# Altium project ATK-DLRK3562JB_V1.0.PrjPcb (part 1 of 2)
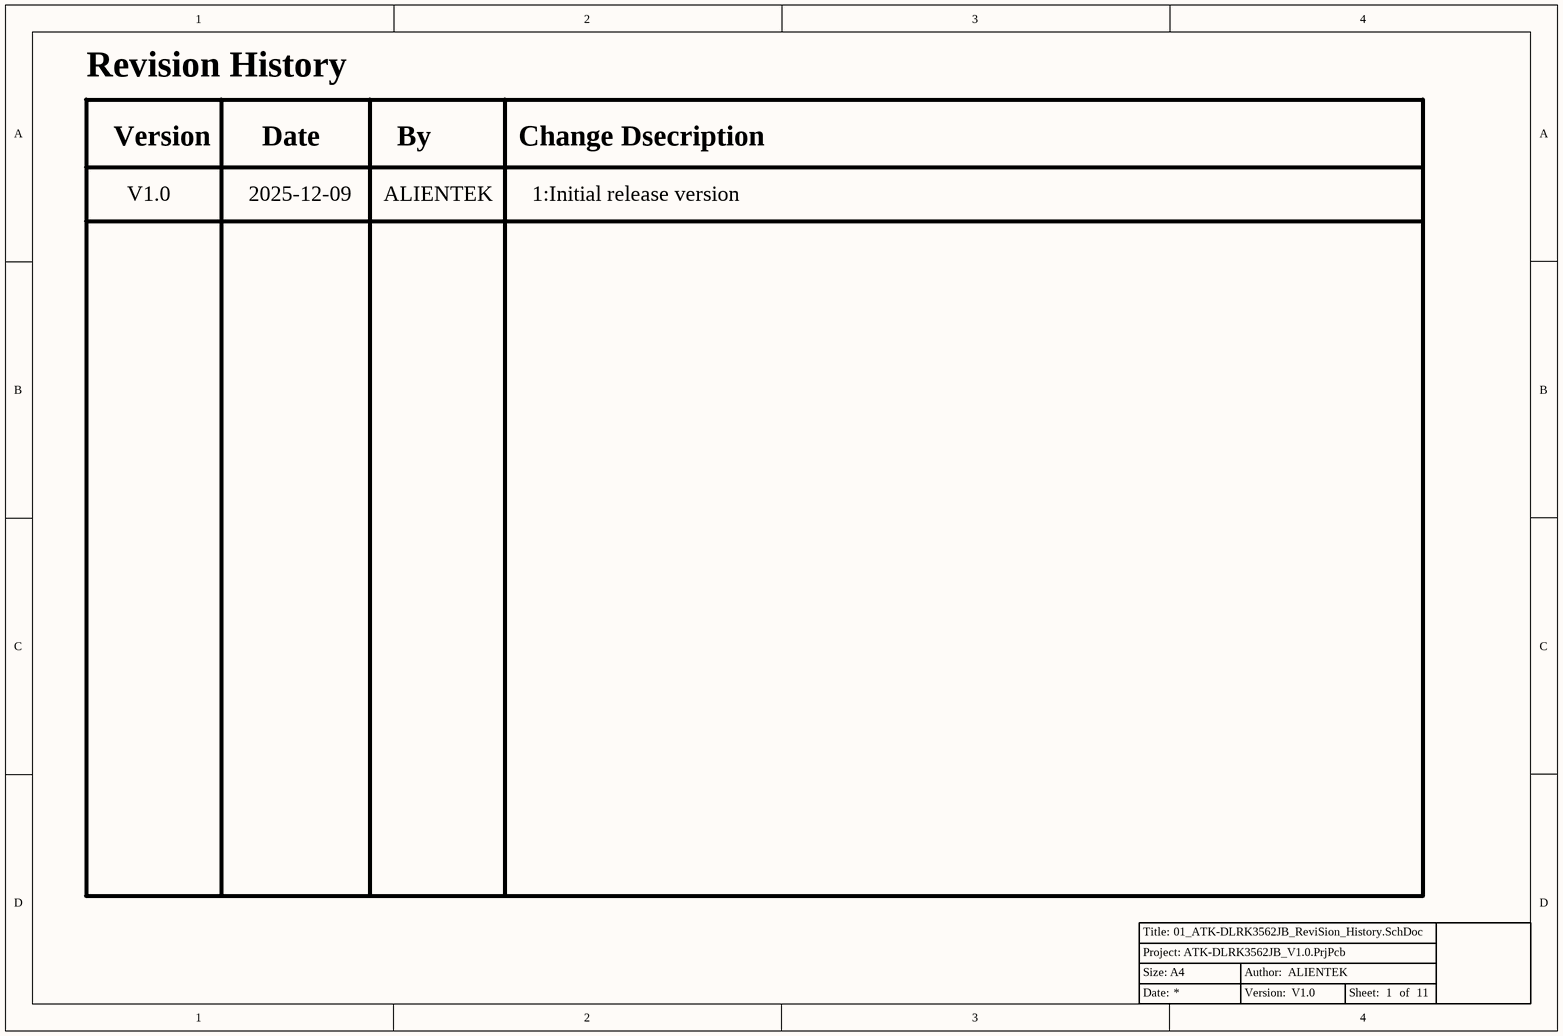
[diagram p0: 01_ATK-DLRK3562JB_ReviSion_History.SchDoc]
11 sheets, 441 parts. Net scope: global (net labels, ports and power ports of the same name join across sheets).
Sheets:
  01_ATK-DLRK3562JB_ReviSion_History.SchDoc
  02_ATK-DLRK3562JB_CORE_BOARD.SchDoc
  03_ATK-DLRK3562JB_POWER_UART.SchDoc
  04_ATK-DLRK3562JB_DEVICE1.SchDoc
  05_ATK-DLRK3562JB_DEVICE2.SchDoc
  06_ATK-DLRK3562JB_4G_HUB.SchDoc
  07_ATK-DLRK3562JB_WIFI_TF_OTG_PINOUT.SchDoc
  08_ATK-DLRK3562JB_PCIE_AUDIO.SchDoc
  09_ATK-DLRK3562JB_LCD_CAMERA.SchDoc
  10_ATK-DLRK3562JB_RMII_NET.SchDoc
  11_ATK-DLRK3562JB_RGMII_NET.SchDoc

## Sheet 01_ATK-DLRK3562JB_ReviSion_History.SchDoc
size A4; Author: ALIENTEK; Revision: 0; SheetNumber: 1; SheetTotal: 11; Version: V1.0; SheetSize: A4

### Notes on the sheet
- Revision History
- Version
- Date
- By
- Change Dsecription
- V1.0
- 2025-12-09
- ALIENTEK
- 1:Initial release version

## Sheet 02_ATK-DLRK3562JB_CORE_BOARD.SchDoc
size A3; Date: 13; Author: ALIENTEK; Revision: 0; SheetNumber: 2; SheetTotal: 11; Version: V1.0; SheetSize: A3
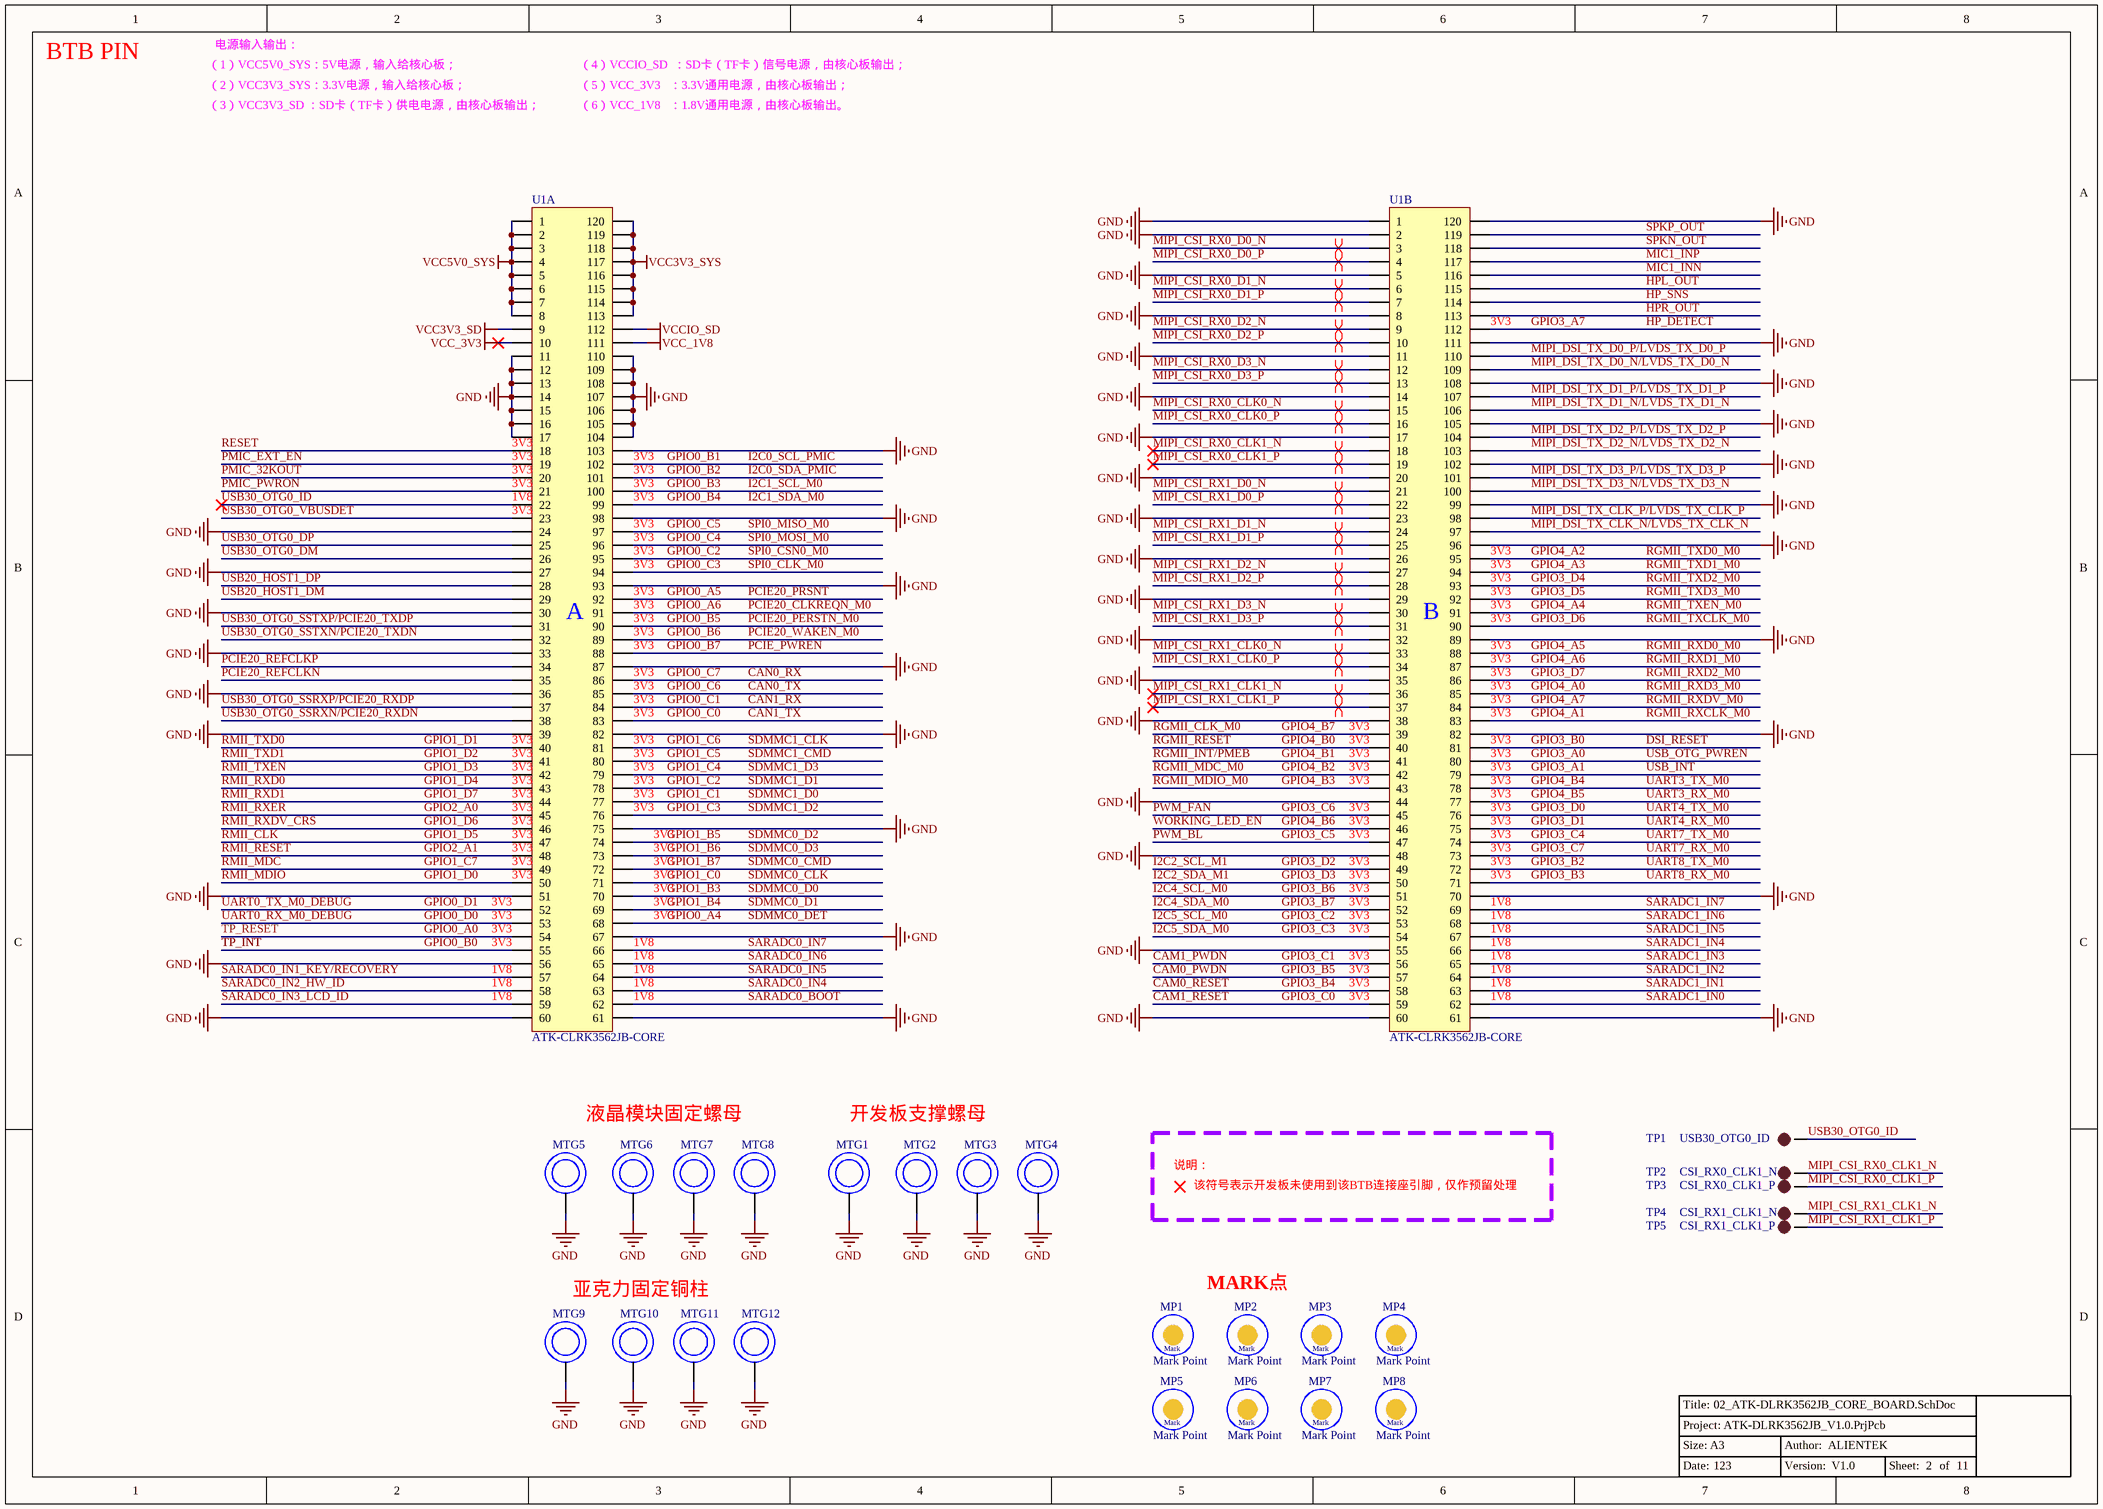
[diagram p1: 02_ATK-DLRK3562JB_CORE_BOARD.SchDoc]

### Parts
MP1  Mark Point  [FD_MARK]
MP2  Mark Point  [FD_MARK]
MP3  Mark Point  [FD_MARK]
MP4  Mark Point  [FD_MARK]
MP5  Mark Point  [FD_MARK]
MP6  Mark Point  [FD_MARK]
MP7  Mark Point  [FD_MARK]
MP8  Mark Point  [FD_MARK]
MTG1  螺母(M3*6,贴片螺母柱,白色,SMTSO-M3-6ET)  [M3-6ET]  (value not drawn)
MTG2  螺母(M3*6,贴片螺母柱,白色,SMTSO-M3-6ET)  [M3-6ET]  (value not drawn)
MTG3  螺母(M3*6,贴片螺母柱,白色,SMTSO-M3-6ET)  [M3-6ET]  (value not drawn)
MTG4  螺母(M3*6,贴片螺母柱,白色,SMTSO-M3-6ET)  [M3-6ET]  (value not drawn)
MTG5  螺母(M3*6,贴片螺母柱,白色,SMTSO-M3-6ET)  [M3*23+6]  (value not drawn)
MTG6  螺母(M3*6,贴片螺母柱,白色,SMTSO-M3-6ET)  [M3*23+6]  (value not drawn)
MTG7  螺母(M3*6,贴片螺母柱,白色,SMTSO-M3-6ET)  [M3*23+6]  (value not drawn)
MTG8  螺母(M3*6,贴片螺母柱,白色,SMTSO-M3-6ET)  [M3*23+6]  (value not drawn)
MTG9  螺母(M3*6,贴片螺母柱,白色,SMTSO-M3-6ET)  [M3-6ET]  (value not drawn)
MTG10  螺母(M3*6,贴片螺母柱,白色,SMTSO-M3-6ET)  [M3-6ET]  (value not drawn)
MTG11  螺母(M3*6,贴片螺母柱,白色,SMTSO-M3-6ET)  [M3-6ET]  (value not drawn)
MTG12  螺母(M3*6,贴片螺母柱,白色,SMTSO-M3-6ET)  [M3-6ET]  (value not drawn)
TP1  USB30_OTG0_ID  [TEST 1]
TP2  CSI_RX0_CLK1_N  [TEST 1]
TP3  CSI_RX0_CLK1_P  [TEST 1]
TP4  CSI_RX1_CLK1_N  [TEST 1]
TP5  CSI_RX1_CLK1_P  [TEST 1]
U1  ATK-CLRK3562JB-CORE  [ATK-CLRK3562JB-CORE]  (parts A,B of 2)

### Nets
GND: MTG1.1 MTG2.1 MTG3.1 MTG4.1 MTG5.1 MTG6.1 MTG7.1 MTG8.1 MTG9.1 MTG10.1 MTG11.1 MTG12.1 U1.A11(11) U1.A12(12) U1.A13(13) U1.A14(14) U1.A15(15) U1.A16(16) U1.A17(17) U1.A24(24) U1.A27(27) U1.A30(30) U1.A33(33) U1.A36(36) U1.A39(39) U1.A51(51) U1.A56(56) U1.A60(60) U1.A61(61) U1.A67(67) U1.A75(75) U1.A82(82) U1.A87(87) U1.A93(93) U1.A98(98) U1.A103(103) U1.A104(104) U1.A105(105) U1.A106(106) U1.A107(107) U1.A108(108) U1.A109(109) U1.A110(110) U1.B1(1) U1.B2(2) U1.B5(5) U1.B8(8) U1.B11(11) U1.B14(14) U1.B17(17) U1.B20(20) U1.B23(23) U1.B26(26) U1.B29(29) U1.B32(32) U1.B35(35) U1.B38(38) U1.B44(44) U1.B48(48) U1.B55(55) U1.B60(60) U1.B61(61) U1.B70(70) U1.B82(82) U1.B89(89) U1.B96(96) U1.B99(99) U1.B102(102) U1.B105(105) U1.B108(108) U1.B111(111) U1.B120(120)
VCC3V3_SD: U1.A9(9)
VCC3V3_SYS: U1.A113(113) U1.A114(114) U1.A115(115) U1.A116(116) U1.A117(117) U1.A118(118) U1.A119(119) U1.A120(120)
VCC5V0_SYS: U1.A1(1) U1.A2(2) U1.A3(3) U1.A4(4) U1.A5(5) U1.A6(6) U1.A7(7) U1.A8(8)
VCC_1V8: U1.A111(111)
VCC_3V3: U1.A10(10)
VCCIO_SD: U1.A112(112)
CAM0_PWDN: U1.B57(57)  [also labelled GPIO3_B5]
CAM0_RESET: U1.B58(58)  [also labelled GPIO3_B4]
CAM1_PWDN: U1.B56(56)  [also labelled GPIO3_C1]
CAM1_RESET: U1.B59(59)  [also labelled GPIO3_C0]
CAN0_RX: U1.A86(86)  [also labelled GPIO0_C7]
CAN0_TX: U1.A85(85)  [also labelled GPIO0_C6]
CAN1_RX: U1.A84(84)  [also labelled GPIO0_C1]
CAN1_TX: U1.A83(83)  [also labelled GPIO0_C0]
DSI_RESET: U1.B81(81)  [also labelled GPIO3_B0]
GPIO0_A0: U1.A54(54)  [also labelled TP_RESET]
GPIO0_A4: U1.A68(68)  [also labelled SDMMC0_DET]
GPIO0_A5: U1.A92(92)  [also labelled PCIE20_PRSNT]
GPIO0_A6: U1.A91(91)  [also labelled PCIE20_CLKREQN_M0]
GPIO0_B0: U1.A55(55)  [also labelled TP_INT]
GPIO0_B1: U1.A102(102)  [also labelled I2C0_SCL_PMIC]
GPIO0_B2: U1.A101(101)  [also labelled I2C0_SDA_PMIC]
GPIO0_B3: U1.A100(100)  [also labelled I2C1_SCL_M0]
GPIO0_B4: U1.A99(99)  [also labelled I2C1_SDA_M0]
GPIO0_B5: U1.A90(90)  [also labelled PCIE20_PERSTN_M0]
GPIO0_B6: U1.A89(89)  [also labelled PCIE20_WAKEN_M0]
GPIO0_B7: U1.A88(88)  [also labelled PCIE_PWREN]
GPIO0_C2: U1.A95(95)  [also labelled SPI0_CSN0_M0]
GPIO0_C3: U1.A94(94)  [also labelled SPI0_CLK_M0]
GPIO0_C4: U1.A96(96)  [also labelled SPI0_MOSI_M0]
GPIO0_C5: U1.A97(97)  [also labelled SPI0_MISO_M0]
GPIO0_D0: U1.A53(53)  [also labelled UART0_RX_M0_DEBUG]
GPIO0_D1: U1.A52(52)  [also labelled UART0_TX_M0_DEBUG]
GPIO1_B3: U1.A70(70)  [also labelled SDMMC0_D0]
GPIO1_B4: U1.A69(69)  [also labelled SDMMC0_D1]
GPIO1_B5: U1.A74(74)  [also labelled SDMMC0_D2]
GPIO1_B6: U1.A73(73)  [also labelled SDMMC0_D3]
GPIO1_B7: U1.A72(72)  [also labelled SDMMC0_CMD]
GPIO1_C0: U1.A71(71)  [also labelled SDMMC0_CLK]
GPIO1_C1: U1.A77(77)  [also labelled SDMMC1_D0]
GPIO1_C2: U1.A78(78)  [also labelled SDMMC1_D1]
GPIO1_C3: U1.A76(76)  [also labelled SDMMC1_D2]
GPIO1_C4: U1.A79(79)  [also labelled SDMMC1_D3]
GPIO1_C5: U1.A80(80)  [also labelled SDMMC1_CMD]
GPIO1_C6: U1.A81(81)  [also labelled SDMMC1_CLK]
GPIO1_C7: U1.A49(49)  [also labelled RMII_MDC]
GPIO1_D0: U1.A50(50)  [also labelled RMII_MDIO]
GPIO1_D1: U1.A40(40)  [also labelled RMII_TXD0]
GPIO1_D2: U1.A41(41)  [also labelled RMII_TXD1]
GPIO1_D3: U1.A42(42)  [also labelled RMII_TXEN]
GPIO1_D4: U1.A43(43)  [also labelled RMII_RXD0]
GPIO1_D5: U1.A47(47)  [also labelled RMII_CLK]
GPIO1_D6: U1.A46(46)  [also labelled RMII_RXDV_CRS]
GPIO1_D7: U1.A44(44)  [also labelled RMII_RXD1]
GPIO2_A0: U1.A45(45)  [also labelled RMII_RXER]
GPIO2_A1: U1.A48(48)  [also labelled RMII_RESET]
GPIO3_A0: U1.B80(80)  [also labelled USB_OTG_PWREN]
GPIO3_A1: U1.B79(79)  [also labelled USB_INT]
GPIO3_A7: U1.B112(112)  [also labelled HP_DETECT]
GPIO3_B2: U1.B72(72)  [also labelled UART8_TX_M0]
GPIO3_B3: U1.B71(71)  [also labelled UART8_RX_M0]
GPIO3_B6: U1.B51(51)  [also labelled I2C4_SCL_M0]
GPIO3_B7: U1.B52(52)  [also labelled I2C4_SDA_M0]
GPIO3_C2: U1.B53(53)  [also labelled I2C5_SCL_M0]
GPIO3_C3: U1.B54(54)  [also labelled I2C5_SDA_M0]
GPIO3_C4: U1.B74(74)  [also labelled UART7_TX_M0]
GPIO3_C5: U1.B47(47)  [also labelled PWM_BL]
GPIO3_C6: U1.B45(45)  [also labelled PWM_FAN]
GPIO3_C7: U1.B73(73)  [also labelled UART7_RX_M0]
GPIO3_D0: U1.B76(76)  [also labelled UART4_TX_M0]
GPIO3_D1: U1.B75(75)  [also labelled UART4_RX_M0]
GPIO3_D2: U1.B49(49)  [also labelled I2C2_SCL_M1]
GPIO3_D3: U1.B50(50)  [also labelled I2C2_SDA_M1]
GPIO3_D4: U1.B93(93)  [also labelled RGMII_TXD2_M0]
GPIO3_D5: U1.B92(92)  [also labelled RGMII_TXD3_M0]
GPIO3_D6: U1.B90(90)  [also labelled RGMII_TXCLK_M0]
GPIO3_D7: U1.B86(86)  [also labelled RGMII_RXD2_M0]
GPIO4_A0: U1.B85(85)  [also labelled RGMII_RXD3_M0]
GPIO4_A1: U1.B83(83)  [also labelled RGMII_RXCLK_M0]
GPIO4_A2: U1.B95(95)  [also labelled RGMII_TXD0_M0]
GPIO4_A3: U1.B94(94)  [also labelled RGMII_TXD1_M0]
GPIO4_A4: U1.B91(91)  [also labelled RGMII_TXEN_M0]
GPIO4_A5: U1.B88(88)  [also labelled RGMII_RXD0_M0]
GPIO4_A6: U1.B87(87)  [also labelled RGMII_RXD1_M0]
GPIO4_A7: U1.B84(84)  [also labelled RGMII_RXDV_M0]
GPIO4_B0: U1.B40(40)  [also labelled RGMII_RESET]
GPIO4_B1: U1.B41(41)  [also labelled RGMII_INT/PMEB]
GPIO4_B2: U1.B42(42)  [also labelled RGMII_MDC_M0]
GPIO4_B3: U1.B43(43)  [also labelled RGMII_MDIO_M0]
GPIO4_B4: U1.B78(78)  [also labelled UART3_TX_M0]
GPIO4_B5: U1.B77(77)  [also labelled UART3_RX_M0]
GPIO4_B6: U1.B46(46)  [also labelled WORKING_LED_EN]
GPIO4_B7: U1.B39(39)  [also labelled RGMII_CLK_M0]
HP_SNS: U1.B114(114)
HPL_OUT: U1.B115(115)
HPR_OUT: U1.B113(113)
MIC1_INN: U1.B116(116)
MIC1_INP: U1.B117(117)
MIPI_CSI_RX0_CLK0_N: U1.B15(15)
MIPI_CSI_RX0_CLK0_P: U1.B16(16)
MIPI_CSI_RX0_CLK1_N: TP2.1 U1.B18(18)
MIPI_CSI_RX0_CLK1_P: TP3.1 U1.B19(19)
MIPI_CSI_RX0_D0_N: U1.B3(3)
MIPI_CSI_RX0_D0_P: U1.B4(4)
MIPI_CSI_RX0_D1_N: U1.B6(6)
MIPI_CSI_RX0_D1_P: U1.B7(7)
MIPI_CSI_RX0_D2_N: U1.B9(9)
MIPI_CSI_RX0_D2_P: U1.B10(10)
MIPI_CSI_RX0_D3_N: U1.B12(12)
MIPI_CSI_RX0_D3_P: U1.B13(13)
MIPI_CSI_RX1_CLK0_N: U1.B33(33)
MIPI_CSI_RX1_CLK0_P: U1.B34(34)
MIPI_CSI_RX1_CLK1_N: TP4.1 U1.B36(36)
MIPI_CSI_RX1_CLK1_P: TP5.1 U1.B37(37)
MIPI_CSI_RX1_D0_N: U1.B21(21)
MIPI_CSI_RX1_D0_P: U1.B22(22)
MIPI_CSI_RX1_D1_N: U1.B24(24)
MIPI_CSI_RX1_D1_P: U1.B25(25)
MIPI_CSI_RX1_D2_N: U1.B27(27)
MIPI_CSI_RX1_D2_P: U1.B28(28)
MIPI_CSI_RX1_D3_N: U1.B30(30)
MIPI_CSI_RX1_D3_P: U1.B31(31)
MIPI_DSI_TX_CLK_N/LVDS_TX_CLK_N: U1.B97(97)
MIPI_DSI_TX_CLK_P/LVDS_TX_CLK_P: U1.B98(98)
MIPI_DSI_TX_D0_N/LVDS_TX_D0_N: U1.B109(109)
MIPI_DSI_TX_D0_P/LVDS_TX_D0_P: U1.B110(110)
MIPI_DSI_TX_D1_N/LVDS_TX_D1_N: U1.B106(106)
MIPI_DSI_TX_D1_P/LVDS_TX_D1_P: U1.B107(107)
MIPI_DSI_TX_D2_N/LVDS_TX_D2_N: U1.B103(103)
MIPI_DSI_TX_D2_P/LVDS_TX_D2_P: U1.B104(104)
MIPI_DSI_TX_D3_N/LVDS_TX_D3_N: U1.B100(100)
MIPI_DSI_TX_D3_P/LVDS_TX_D3_P: U1.B101(101)
PCIE20_REFCLKN: U1.A35(35)
PCIE20_REFCLKP: U1.A34(34)
PMIC_32KOUT: U1.A20(20)
PMIC_EXT_EN: U1.A19(19)
PMIC_PWRON: U1.A21(21)
RESET: U1.A18(18)
SARADC0_BOOT: U1.A62(62)
SARADC0_IN1_KEY/RECOVERY: U1.A57(57)
SARADC0_IN2_HW_ID: U1.A58(58)
SARADC0_IN3_LCD_ID: U1.A59(59)
SARADC0_IN4: U1.A63(63)
SARADC0_IN5: U1.A64(64)
SARADC0_IN6: U1.A65(65)
SARADC0_IN7: U1.A66(66)
SARADC1_IN0: U1.B62(62)
SARADC1_IN1: U1.B63(63)
SARADC1_IN2: U1.B64(64)
SARADC1_IN3: U1.B65(65)
SARADC1_IN4: U1.B66(66)
SARADC1_IN5: U1.B67(67)
SARADC1_IN6: U1.B68(68)
SARADC1_IN7: U1.B69(69)
SPKN_OUT: U1.B118(118)
SPKP_OUT: U1.B119(119)
USB20_HOST1_DM: U1.A29(29)
USB20_HOST1_DP: U1.A28(28)
USB30_OTG0_DM: U1.A26(26)
USB30_OTG0_DP: U1.A25(25)
USB30_OTG0_ID: TP1.1 U1.A22(22)
USB30_OTG0_SSRXN/PCIE20_RXDN: U1.A38(38)
USB30_OTG0_SSRXP/PCIE20_RXDP: U1.A37(37)
USB30_OTG0_SSTXN/PCIE20_TXDN: U1.A32(32)
USB30_OTG0_SSTXP/PCIE20_TXDP: U1.A31(31)
USB30_OTG0_VBUSDET: U1.A23(23)

Not connected (* = marked no-connect by the designer): MP1 1; MP2 1; MP3 1; MP4 1; MP5 1; MP6 1; MP7 1; MP8 1

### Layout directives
differential pair: MIPI_CSI_RX0_CLK0_N, MIPI_CSI_RX0_CLK0_P, MIPI_CSI_RX0_CLK1_N, MIPI_CSI_RX0_CLK1_P, MIPI_CSI_RX0_D0_N, MIPI_CSI_RX0_D0_P, MIPI_CSI_RX0_D1_N, MIPI_CSI_RX0_D1_P, MIPI_CSI_RX0_D2_N, MIPI_CSI_RX0_D2_P, MIPI_CSI_RX0_D3_N, MIPI_CSI_RX0_D3_P, MIPI_CSI_RX1_CLK0_N, MIPI_CSI_RX1_CLK0_P, MIPI_CSI_RX1_CLK1_N, MIPI_CSI_RX1_CLK1_P, MIPI_CSI_RX1_D0_N, MIPI_CSI_RX1_D0_P, MIPI_CSI_RX1_D1_N, MIPI_CSI_RX1_D1_P, MIPI_CSI_RX1_D2_N, MIPI_CSI_RX1_D2_P, MIPI_CSI_RX1_D3_N, MIPI_CSI_RX1_D3_P

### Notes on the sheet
- 电源输入输出：
- BTB PIN
- （1）VCC5V0_SYS：5V电源，输入给核心板；
- （2）VCC3V3_SYS：3.3V电源，输入给核心板；
- （3）VCC3V3_SD ：SD卡（TF卡）供电电源，由核心板输出；
- （4）VCCIO_SD  ：SD卡（TF卡）信号电源，由核心板输出；
- （5）VCC_3V3   ：3.3V通用电源，由核心板输出；
- （6）VCC_1V8   ：1.8V通用电源，由核心板输出。
- (near U1) 3V3
- (near U1) 1V8
- 液晶模块固定螺母
- 开发板支撑螺母
- 说明：
- 该符号表示开发板未使用到该BTB连接座引脚，仅作预留处理
- 亚克力固定铜柱
- MARK点

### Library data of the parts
MP1-MP8 = MARK
MTG1-MTG12 = MTG_Hole_1: 301020001
TP1-TP5 = TEST: 测试点; 版权归属: 正点原子; Parameter: 未分类器件
U1 = AXK5A2137YG-120P-母座带柱

## Sheet 03_ATK-DLRK3562JB_POWER_UART.SchDoc
size A4; Author: ALIENTEK; Revision: 0; SheetNumber: 3; SheetTotal: 11; Version: V1.0; SheetSize: A4
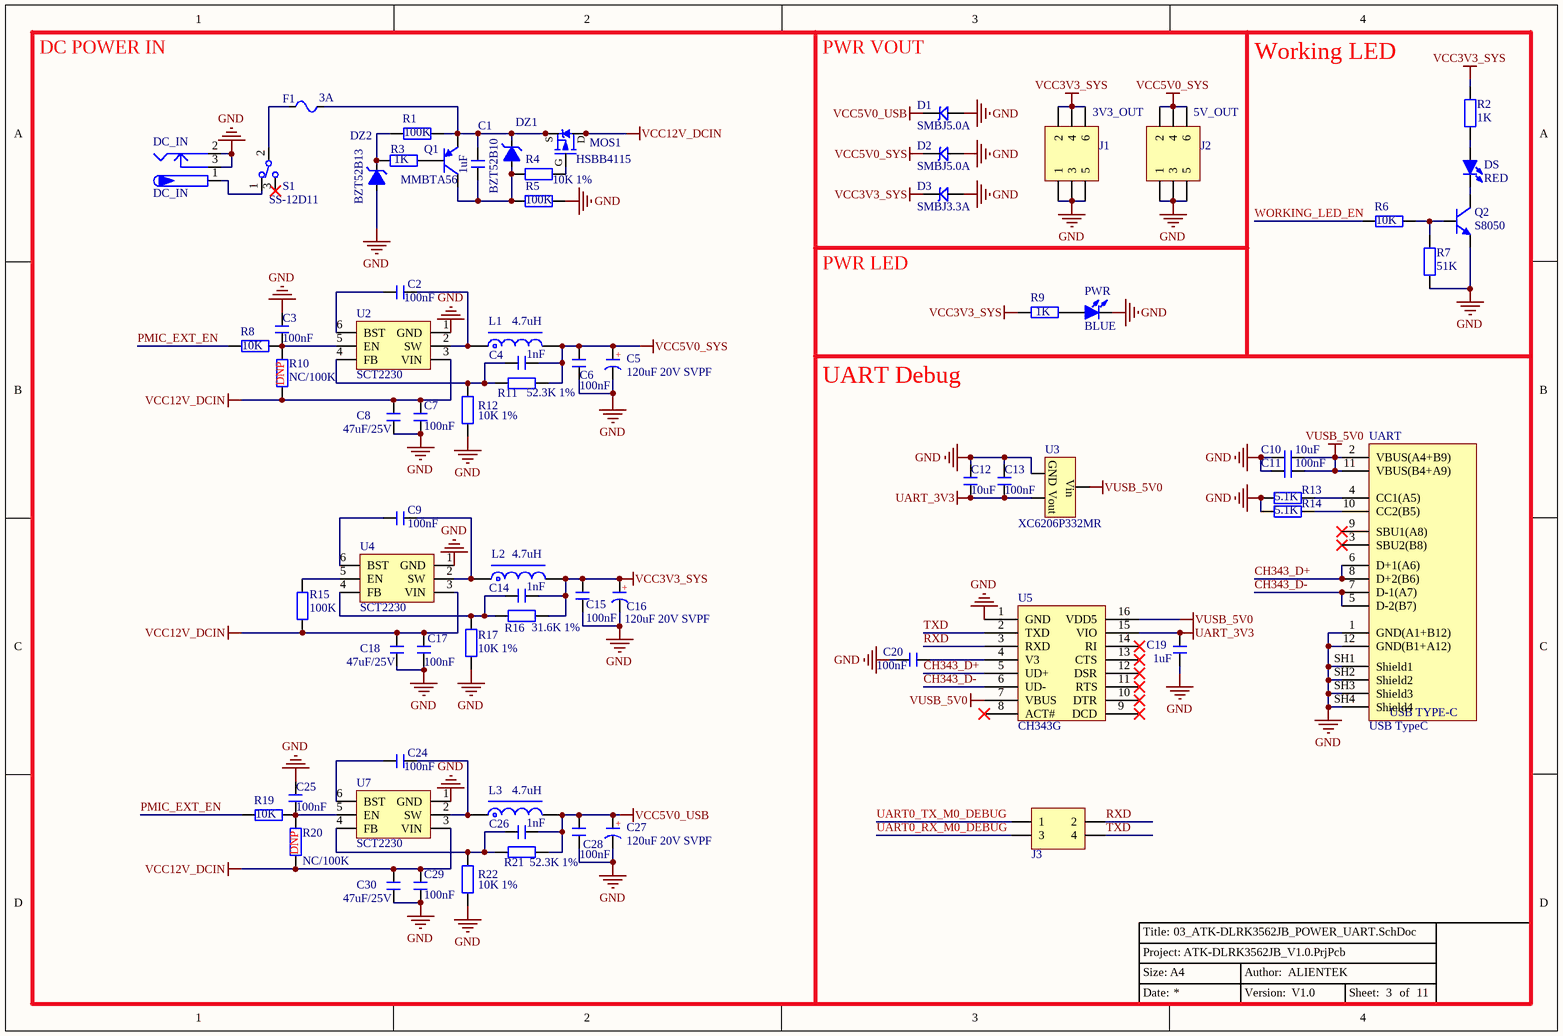
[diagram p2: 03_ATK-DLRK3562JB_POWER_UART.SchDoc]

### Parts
C1  1uF  [C 0603]
C2  100nF  [C 0402]
C3  100nF  [C 0402]
C4  1nF  [C 0402]
C5  120uF 20V SVPF  [CM D(6.3*7.7)]
C6  100nF  [C 0402]
C7  100nF  [C 0402]
C8  47uF/25V  [C 1206]
C9  100nF  [C 0402]
C10  10uF  [C 0805]
C11  100nF  [C 0402]
C12  10uF  [C 0805]
C13  100nF  [C 0402]
C14  1nF  [C 0402]
C15  100nF  [C 0402]
C16  120uF 20V SVPF  [CM D(6.3*7.7)]
C17  100nF  [C 0402]
C18  47uF/25V  [C 1206]
C19  1uF  [C 0603]
C20  100nF  [C 0402]
C24  100nF  [C 0402]
C25  100nF  [C 0402]
C26  1nF  [C 0402]
C27  120uF 20V SVPF  [CM D(6.3*7.7)]
C28  100nF  [C 0402]
C29  100nF  [C 0402]
C30  47uF/25V  [C 1206]
D1  SMBJ5.0A  [SMBJ]
D2  SMBJ5.0A  [SMBJ]
D3  SMBJ3.3A  [SMBJ]
DC_IN  DC_IN  [DC10B]
DS  RED  [LED 0805 Red]
DZ1  BZT52B10  [SOD-123]
DZ2  BZT52B13  [SOD-123]
F1  3A  [FU 1812]
J1  3V3_OUT  [Header 2.54 2X3P]
J2  5V_OUT  [Header 2.54 2X3P]
J3  Header2X2  [Header 2.54 2X2P]  (value not drawn)
L1  4.7uH  [L-SMD-0420]
L2  4.7uH  [L-SMD-0420]
L3  4.7uH  [L-SMD-0420]
MOS1  HSBB4115  [DFN8_ 3x3]
PWR  BLUE  [LED 0805B]
Q1  MMBTA56  [SOT23-3N]
Q2  S8050  [SOT23-3N]
R1  100K  [R 0402]
R2  1K  [R 0402]
R3  1K  [R 0402]
R4  10K 1%  [R 0402]
R5  100K  [R 0402]
R6  10K  [R 0402]
R7  51K  [R 0402]
R8  10K  [R 0402]
R9  1K  [R 0402]
R10  NC/100K  [R 0402]
R11  52.3K 1%  [R 0402]
R12  10K 1%  [R 0402]
R13  5.1K  [R 0402]
R14  5.1K  [R 0402]
R15  100K  [R 0402]
R16  31.6K 1%  [R 0402]
R17  10K 1%  [R 0402]
R19  10K  [R 0402]
R20  NC/100K  [R 0402]
R21  52.3K 1%  [R 0402]
R22  10K 1%  [R 0402]
S1  SS-12D11  [SS-12D06]
U2  SCT2230  [SOT23-6N]
U3  XC6206P332MR  [SOT23-3L]
U4  SCT2230  [SOT23-6N]
U5  CH343G  [SOP16_N]
U7  SCT2230  [SOT23-6N]
UART  USB TypeC  [USB2.0-TYPE-C-16P]

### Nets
GND: C3.2 C5.2(K) C6.2 C7.1 C8.1 C10.1 C11.1 C12.2 C13.2 C15.2 C16.2(K) C17.1 C18.1 C19.2 C20.2 C25.2 C27.2(K) C28.2 C29.1 C30.1 D1.1 D2.1 D3.1 DC_IN.2 DC_IN.3 DZ2.1(A) J1.1 J1.3 J1.5 J2.1 J2.3 J2.5 PWR.2(K) Q2.2(E) R5.2 R7.1 R12.2 R13.1 R14.1 R17.2 R22.2 U2.1(GND) U3.1(GND) U4.1(GND) U5.1(GND) U7.1(GND) UART.1(GND(A1+B12)) UART.12(GND(B1+A12)) UART.SH1(Shield1) UART.SH2(Shield2) UART.SH3(Shield3) UART.SH4(Shield4)
UART_3V3: C12.1 C13.1 C19.1 U3.2(Vout) U5.15(VIO)
VCC3V3_SYS: C14.1 C15.1 C16.1(A) D3.2 J1.2 J1.4 J1.6 L2.2 R2.2 R9.2 R16.2
VCC5V0_SYS: C4.1 C5.1(A) C6.1 D2.2 J2.2 J2.4 J2.6 L1.2 R11.2
VCC5V0_USB: C26.1 C27.1(A) C28.1 D1.2 L3.2 R21.2
VCC12V_DCIN: C7.2 C8.2 C17.2 C18.2 C29.2 C30.2 MOS1.5(D) MOS1.6(D) MOS1.7(D) MOS1.8(D) R10.1 R15.2 R20.2 U2.3(VIN) U4.3(VIN) U7.3(VIN)
VUSB_5V0: C10.2 C11.2 U3.3(Vin) U5.7(VBUS) U5.16(VDD5) UART.2(VBUS(A4+B9)) UART.11(VBUS(B4+A9))
CH343_D+: U5.5(UD+) UART.6(D+1(A6)) UART.8(D+2(B6))
CH343_D-: U5.6(UD-) UART.5(D-2(B7)) UART.7(D-1(A7))
PMIC_EXT_EN: R8.2 R19.2
RXD: J3.2 U5.3(RXD)
TXD: J3.4 U5.2(TXD)
UART0_RX_M0_DEBUG: J3.3  [project net GPIO0_D0]
UART0_TX_M0_DEBUG: J3.1  [project net GPIO0_D1]
WORKING_LED_EN: R6.2  [project net GPIO4_B6]
NetC1_1: C1.1 DZ1.2(K) F1.1 MOS1.1(S) MOS1.2(S) MOS1.3(G) Q1.2(E) R1.1
NetC1_2: C1.2 DZ1.1(A) Q1.3(C) R4.1 R5.1
NetC2_1: C2.1 U2.6(BST)
NetC2_2: C2.2 L1.1 U2.2(SW)
NetC3_1: C3.1 R8.1 R10.2 U2.5(EN)
NetC4_2: C4.2 R11.1 R12.1 U2.4(FB)
NetC9_1: C9.1 U4.6(BST)
NetC9_2: C9.2 L2.1 U4.2(SW)
NetC14_2: C14.2 R16.1 R17.1 U4.4(FB)
NetC20_1: C20.1 U5.4(V3)
NetC24_1: C24.1 U7.6(BST)
NetC24_2: C24.2 L3.1 U7.2(SW)
NetC25_1: C25.1 R19.1 R20.1 U7.5(EN)
NetC26_2: C26.2 R21.1 R22.1 U7.4(FB)
NetDC_IN_1: DC_IN.1 S1.1
NetDS_1: DS.1(A) R2.1
NetDS_2: DS.2(K) Q2.3(C)
NetDZ2_2: DZ2.2(K) R1.2 R3.1
NetF1_2: F1.2 S1.2
NetMOS1_4: MOS1.4(G) R4.2
NetPWR_1: PWR.1(A) R9.1
NetQ1_1: Q1.1(B) R3.2
NetQ2_1: Q2.1(B) R6.1 R7.2
NetR13_2: R13.2 UART.4(CC1(A5))
NetR14_2: R14.2 UART.10(CC2(B5))
NetR15_1: R15.1 U4.5(EN)

Not connected (* = marked no-connect by the designer): S1 3*; U5 8(ACT#)* 9(DCD)* 10(DTR)* 11(RTS)* 12(DSR)* 13(CTS)* 14(RI)*; UART 3(SBU2(B8))* 9(SBU1(A8))*

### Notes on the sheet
- DC POWER IN
- PWR VOUT
- Working LED
- PWR LED
- (near R10) DNP
- UART Debug
- (near R20) DNP

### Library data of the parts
C1 C19 = C: 50V 10% 无极性贴片电容; BOM名称: 电容; 版权归属: 正点原子
C2-C4 C6-C9 C14 C15 C17 C18 C24-C26 C28-C30 = C: 无极性贴片电容; 版权归属: 源创客
C5 C16 C27 = C-CM: 贴片电解电容; 版权归属: 源创客
C10-C13 C20 = C: 无极性电容; BOM名称: 无极性贴片电容; 版权归属: 正点原子
D1-D3 = SMBJ: TVS
DC_IN = P-DC: 低压电源接口; BOM名称: DC电源接口; 版权归属: 源创客
DS = LED: BOM名称: 插件LED; 版权归属: 正点原子; Parameter: 发光二极管
DZ1 DZ2 = BZT52BxVx: CJ x.xV / 0.5W稳压管  2%; 版权归属: 正点原子; BOM名称: 二极管(稳压)
F1 = FU: 贴片保险丝; 版权归属: 源创客
J1 J2 = Header 3X2: 3*2P接插件; 版权归属: 正点原子; Parameter: 接插件
J3 = Header 2X2: 2*2P接插件; 版权归属: 正点原子; Parameter: 接插件
L1-L3 = L-CDRH: 功率屏蔽电感; 版权归属: 源创客
MOS1 = HSBB6115: PMOS -60V -8A@-4.5V 33mΩ; BOM名称: MOS管; 版权归属: 正点原子
PWR = LED-SMD: 贴片LED; 版权归属: 源创客
Q1 = 9015-SMD: 低噪放大-PNP型; BOM名称: 三极管; 版权归属: 正点原子; 属性: 50V 0.1A 0.4W 150MHZ
Q2 = 8050-SMD: 高频放大-NPN型; 版权归属: 正点原子; 属性: 40V 1.5A 1W 100MHZ; Parameter: 三极管
R1 R3-R5 = R: 贴片电阻; BOM名称: 电阻; 版权归属: 正点原子
R2 R6 R7 R13 R14 = R: 电阻; BOM名称: 贴片电阻; 版权归属: 正点原子
R8-R12 R15-R17 R19-R22 = R: 贴片电阻; 版权归属: 源创客
S1 = SSW-1P: 1路波动开关; BOM名称: 波动开关; 版权归属: 源创客
U2 U4 U7 = DC JW5060T_6: DC降压芯片
U3 = XC6206: LDO 5.5V 200-300mA; 版权归属: 正点原子; Parameter: 芯片
UART = USB 2.0 Type C: 12P TypeC 母座; 版权归属: 正点原子; Parameter: 接口器件

## Sheet 04_ATK-DLRK3562JB_DEVICE1.SchDoc
size A4; Author: ALIENTEK; Revision: 0; SheetNumber: 4; SheetTotal: 11; Version: V1.0; SheetSize: A4
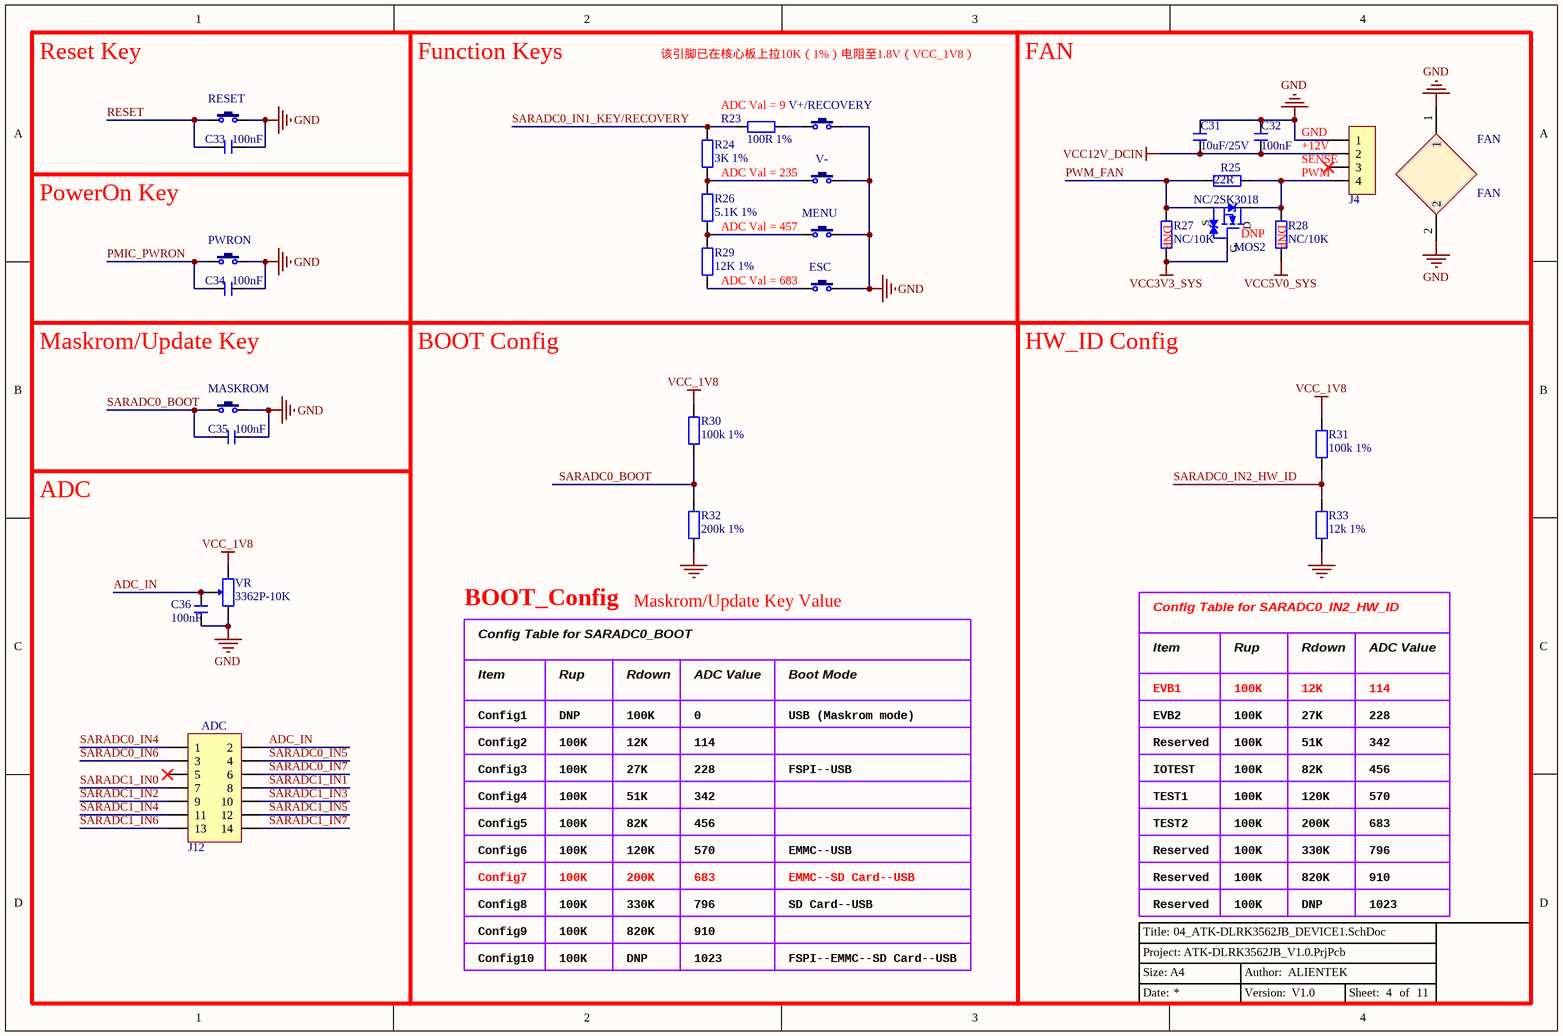
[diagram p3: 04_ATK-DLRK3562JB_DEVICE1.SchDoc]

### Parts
C31  10uF/25V  [C 0805]
C32  100nF  [C 0402]
C33  100nF  [C 0402]
C34  100nF  [C 0402]
C35  100nF  [C 0402]
C36  100nF  [C 0402]
ESC  KEY  [TSW DIP-6*6*5 - 2]  (value not drawn)
FAN  FAN  [40X40MM_FAN_59MM]
J4  FAN-HEADER  [PH2.0-4P V-T]  (value not drawn)
J12  ADC  [Header 2.54 2X7P]
MASKROM  KEY  [TSW DIP-6*6*5 - 2]  (value not drawn)
MENU  KEY  [TSW DIP-6*6*5 - 2]  (value not drawn)
MOS2  NC/2SK3018  [SOT323-3L]
PWRON  KEY  [TSW DIP-6*6*5 - 2]  (value not drawn)
R23  100R 1%  [R 0402]
R24  3K 1%  [R 0402]
R25  22R  [R 0402]
R26  5.1K 1%  [R 0402]
R27  NC/10K  [R 0402]
R28  NC/10K  [R 0402]
R29  12K 1%  [R 0402]
R30  100k 1%  [R 0402]
R31  100k 1%  [R 0402]
R32  200k 1%  [R 0402]
R33  12k 1%  [R 0402]
RESET  KEY  [TSW DIP-6*6*5 - 2]  (value not drawn)
V+/RECOVERY  KEY  [TSW DIP-6*6*5 - 2]  (value not drawn)
V-  KEY  [TSW DIP-6*6*5 - 2]  (value not drawn)
VR  3362P-10K  [3362P]

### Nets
GND: C31.2 C32.2 C33.2 C34.2 C35.2 C36.1 ESC.2 FAN.1 FAN.2 J4.1 MASKROM.2 MENU.2 PWRON.2 R32.2 R33.2 RESET.2 V+/RECOVERY.2 V-.2 VR.1
VCC3V3_SYS: MOS2.1(G) R27.2
VCC5V0_SYS: R28.2
VCC12V_DCIN: C31.1 C32.1 J4.2
VCC_1V8: R30.1 R31.1 VR.3
ADC_IN: C36.2 J12.2 VR.2
PMIC_PWRON: C34.1 PWRON.1
PWM_FAN: MOS2.2(S) R25.1 R27.1  [project net GPIO3_C6]
RESET: C33.1 RESET.1
SARADC0_BOOT: C35.1 MASKROM.1 R30.2 R32.1
SARADC0_IN1_KEY/RECOVERY: R23.2 R24.2
SARADC0_IN2_HW_ID: R31.2 R33.1
SARADC0_IN4: J12.1
SARADC0_IN5: J12.4
SARADC0_IN6: J12.3
SARADC0_IN7: J12.6
SARADC1_IN0: J12.7
SARADC1_IN1: J12.8
SARADC1_IN2: J12.9
SARADC1_IN3: J12.10
SARADC1_IN4: J12.11
SARADC1_IN5: J12.12
SARADC1_IN6: J12.13
SARADC1_IN7: J12.14
NetESC_1: ESC.1 R29.1
NetJ4_4: J4.4 MOS2.3(D) R25.2 R28.1
NetMENU_1: MENU.1 R26.1 R29.2
NetR23_1: R23.1 V+/RECOVERY.1
NetR24_1: R24.1 R26.2 V-.1

Not connected (* = marked no-connect by the designer): J4 3*; J12 5*

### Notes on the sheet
- Reset Key
- Function Keys
- 该引脚已在核心板上拉10K（1%）电阻至1.8V（VCC_1V8）
- (near R23) ADC Val = 9
- FAN
- ADC Val = 235
- (near J4) +12V
- GND
- (near J4) SENSE
- PWM
- PowerOn Key
- ADC Val = 457
- (near R27) DNP
- (near MOS2) DNP
- (near R28) DNP
- ADC Val = 683
- Maskrom/Update Key
- BOOT Config
- HW_ID Config
- ADC
- BOOT_Config
- Config Table for SARADC0_BOOT
- Maskrom/Update Key Value
- Config Table for SARADC0_IN2_HW_ID
- Item
- Rup
- Rdown
- ADC Value
- Config1
- DNP
- 100K
- 0
- USB (Maskrom mode)
- Boot Mode
- EVB1
- EVB2
- 12K
- 27K
- 228
- 114
- Config3
- Config2
- FSPI--USB
- IOTEST
- Reserved
- 82K
- 51K
- 456
- 342
- Config5
- Config6
- Config4
- 120K
- 570
- EMMC--USB
- TEST1
- TEST2
- 330K
- 200K
- 796
- 683
- Config8
- Config7
- EMMC--SD Card--USB
- SD Card--USB
- 820K
- 1023
- 910
- Config10
- Config9
- FSPI--EMMC--SD Card--USB

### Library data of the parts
C31 C32 = C: 无极性电容; BOM名称: 无极性贴片电容; 版权归属: 正点原子
C33-C36 = C: 无极性贴片电容; 版权归属: 正点原子
ESC MASKROM MENU PWRON RESET V+/RECOVERY V- = KEY: 按键; BOM名称: 3x6轻触开关; 版权归属: 正点原子; Parameter: 按键/开关
FAN = FAN: 风扇
J4 = Header 4: 4P接插件; 版权归属: 正点原子; Parameter: 接插件
J12 = Header 7X2: 7*2P接插件; 版权归属: 正点原子; Parameter: 接插件
MOS2 = 2SK3018: NMOS  30V 0.1A@2.5V 8Ω; BOM名称: N沟场效应管; 版权归属: 正点原子; Parameter: MOS管
R23 R24 R26 R29-R33 = R: 电阻; BOM名称: 贴片电阻; 版权归属: 正点原子
R25 R27 R28 = R: 贴片电阻; 版权归属: 正点原子
VR = 3362P-10K: 可调电位器; BOM名称: 插件电位器; 版权归属: 正点原子

## Sheet 05_ATK-DLRK3562JB_DEVICE2.SchDoc
size A4; Author: ALIENTEK; Revision: 0; SheetNumber: 5; SheetTotal: 11; Version: V1.0; SheetSize: A4
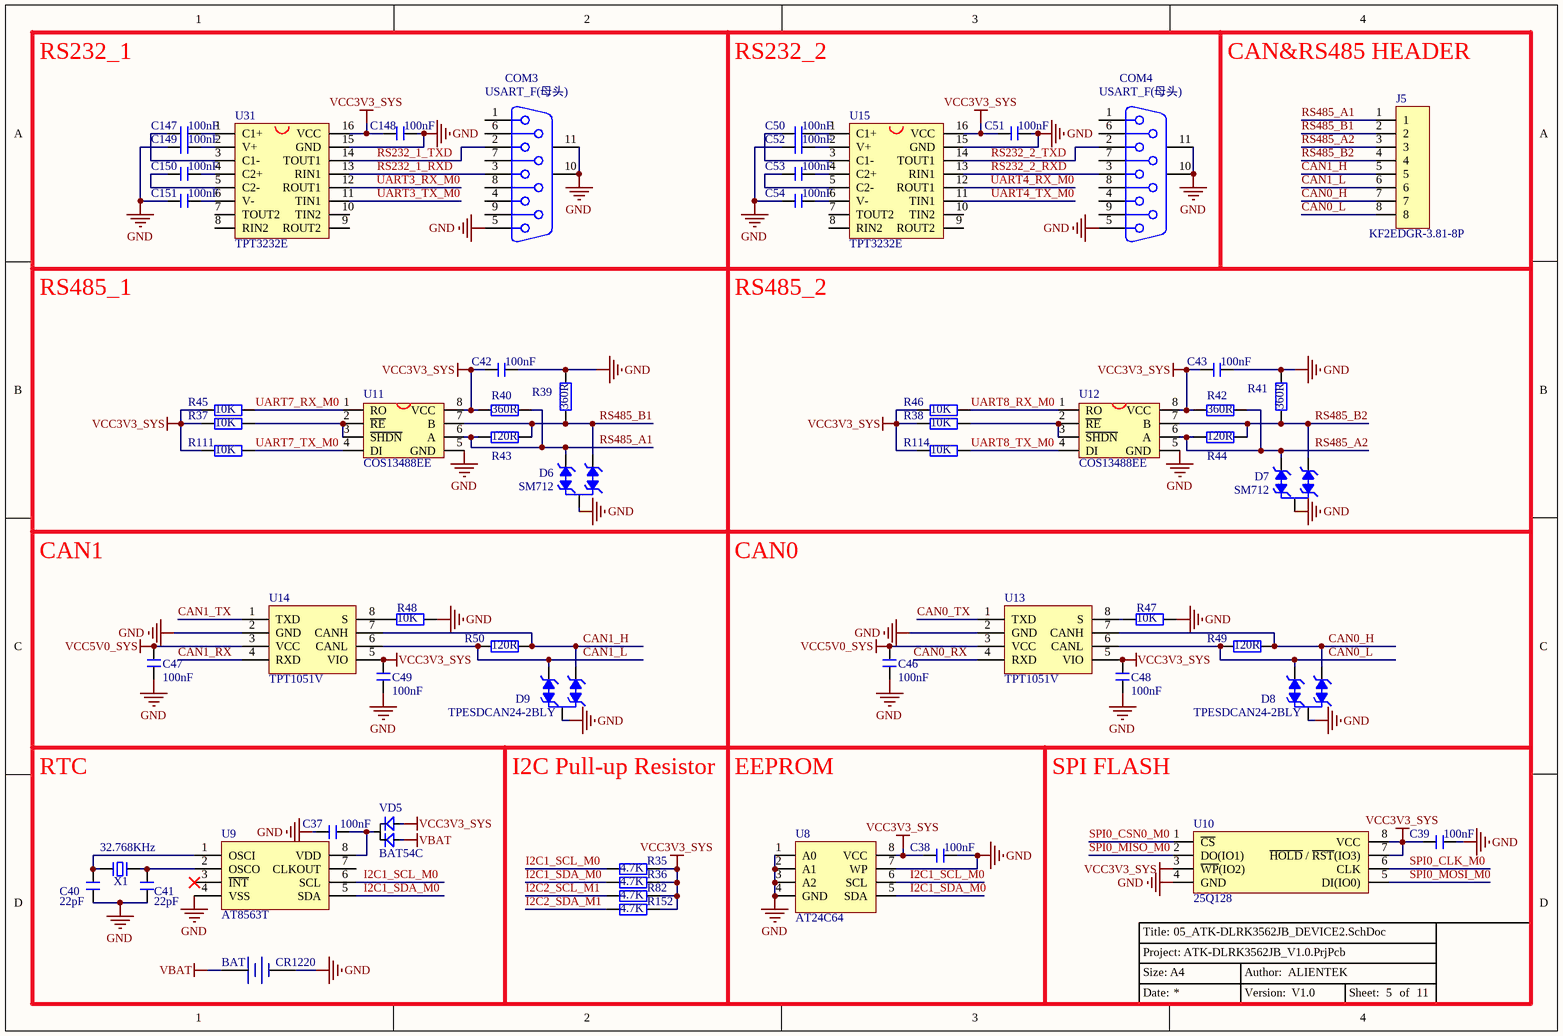
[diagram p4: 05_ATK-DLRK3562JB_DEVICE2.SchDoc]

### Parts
BAT  CR1220  [CR1220_A]
C37  100nF  [C 0402]
C38  100nF  [C 0402]
C39  100nF  [C 0402]
C40  22pF  [C 0402]
C41  22pF  [C 0402]
C42  100nF  [C 0402]
C43  100nF  [C 0402]
C46  100nF  [C 0402]
C47  100nF  [C 0402]
C48  100nF  [C 0402]
C49  100nF  [C 0402]
C50  100nF  [C 0402]
C51  100nF  [C 0402]
C52  100nF  [C 0402]
C53  100nF  [C 0402]
C54  100nF  [C 0402]
C147  100nF  [C 0402]
C148  100nF  [C 0402]
C149  100nF  [C 0402]
C150  100nF  [C 0402]
C151  100nF  [C 0402]
COM3  USART_F(母头)  [DB9/S_A]
COM4  USART_F(母头)  [DB9/S_A]
D6  SM712  [SOT23-3L]
D7  SM712  [SOT23-3L]
D8  TPESDCAN24-2BLY  [SOT23-3L]
D9  TPESDCAN24-2BLY  [SOT23-3L]
J5  KF2EDGR-3.81-8P  [KF2EDGR_3.81_8P]
R35  4.7K  [R 0402]
R36  4.7K  [R 0402]
R37  10K  [R 0402]
R38  10K  [R 0402]
R39  360R  [R 0402]
R40  360R  [R 0402]
R41  360R  [R 0402]
R42  360R  [R 0402]
R43  120R  [R 0402]
R44  120R  [R 0402]
R45  10K  [R 0402]
R46  10K  [R 0402]
R47  10K  [R 0402]
R48  10K  [R 0402]
R49  120R  [R 0402]
R50  120R  [R 0402]
R82  4.7K  [R 0402]
R111  10K  [R 0402]
R114  10K  [R 0402]
R152  4.7K  [R 0402]
U8  AT24C64  [SOP8_N]
U9  AT8563T  [SOP8_N]
U10  25Q128  [SOP8W_N]
U11  COS13488EE  [SOP8_N]
U12  COS13488EE  [SOP8_N]
U13  TPT1051V  [SOP8_N]
U14  TPT1051V  [SOP8_N]
U15  TPT3232E  [SOP16_N]
U31  TPT3232E  [SOP16_N]
VD5  BAT54C  [SOT23-3N]
X1  32.768KHz  [XTAL-3215]

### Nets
GND: BAT.2(DC-) C37.1 C38.1 C39.1 C40.2 C41.2 C42.2 C43.2 C46.2 C47.2 C48.2 C49.2 C51.2 C52.1 C54.1 C148.2 C149.1 C151.1 COM3.5 COM3.10(MH1) COM3.11(MH2) COM4.5 COM4.10(MH1) COM4.11(MH2) D6.3 D7.3 D8.3 D9.3 R39.1 R41.1 R47.2 R48.2 U8.1(A0) U8.2(A1) U8.3(A2) U8.4(GND) U8.7(WP) U9.4(VSS) U10.4(GND) U11.5(GND) U12.5(GND) U13.2(GND) U14.2(GND) U15.15(GND) U31.15(GND)
VBAT: BAT.1(DC+) VD5.1
VCC3V3_SYS: C38.2 C39.2 C42.1 C43.1 C48.1 C49.1 C51.1 C148.1 R35.2 R36.2 R37.2 R38.2 R40.2 R42.2 R45.2 R46.2 R82.2 R111.2 R114.2 R152.2 U8.8(VCC) U10.3(~{WP}(IO2)) U10.7(~{HOLD}_/_~{RST}(IO3)) U10.8(VCC) U11.8(VCC) U12.8(VCC) U13.5(VIO) U14.5(VIO) U15.16(VCC) U31.16(VCC) VD5.2
VCC5V0_SYS: C46.1 C47.1 U13.3(VCC) U14.3(VCC)
CAN0_H: D8.1 J5.7 R49.1 U13.7(CANH)
CAN0_L: D8.2 J5.8 R49.2 U13.6(CANL)
CAN0_RX: U13.4(RXD)
CAN0_TX: U13.1(TXD)
CAN1_H: D9.1 J5.5 R50.1 U14.7(CANH)
CAN1_L: D9.2 J5.6 R50.2 U14.6(CANL)
CAN1_RX: U14.4(RXD)
CAN1_TX: U14.1(TXD)
I2C1_SCL_M0: R35.1 U8.6(SCL) U9.6(SCL)  [project net GPIO0_B3]
I2C1_SDA_M0: R36.1 U8.5(SDA) U9.5(SDA)  [project net GPIO0_B4]
I2C2_SCL_M1: R82.1  [project net GPIO3_D2]
I2C2_SDA_M1: R152.1  [project net GPIO3_D3]
RS232_1_RXD: COM3.3 U31.13(RIN1)
RS232_1_TXD: COM3.2 U31.14(TOUT1)
RS232_2_RXD: COM4.3 U15.13(RIN1)
RS232_2_TXD: COM4.2 U15.14(TOUT1)
RS485_A1: D6.2 J5.1 R40.1 R43.2 U11.6(A)
RS485_A2: D7.2 J5.3 R42.1 R44.2 U12.6(A)
RS485_B1: D6.1 J5.2 R39.2 R43.1 U11.7(B)
RS485_B2: D7.1 J5.4 R41.2 R44.1 U12.7(B)
SPI0_CLK_M0: U10.6(CLK)  [project net GPIO0_C3]
SPI0_CSN0_M0: U10.1(~{CS})  [project net GPIO0_C2]
SPI0_MISO_M0: U10.2(DO(IO1))  [project net GPIO0_C5]
SPI0_MOSI_M0: U10.5(DI(IO0))  [project net GPIO0_C4]
UART3_RX_M0: U31.12(ROUT1)  [project net GPIO4_B5]
UART3_TX_M0: U31.11(TIN1)  [project net GPIO4_B4]
UART4_RX_M0: U15.12(ROUT1)  [project net GPIO3_D1]
UART4_TX_M0: U15.11(TIN1)  [project net GPIO3_D0]
UART7_RX_M0: R45.1 U11.1(RO)  [project net GPIO3_C7]
UART7_TX_M0: R111.1 U11.4(DI)  [project net GPIO3_C4]
UART8_RX_M0: R46.1 U12.1(RO)  [project net GPIO3_B3]
UART8_TX_M0: R114.1 U12.4(DI)  [project net GPIO3_B2]
NetC37_2: C37.2 U9.8(VDD) VD5.3
NetC40_1: C40.1 U9.1(OSCI) X1.1
NetC41_1: C41.1 U9.2(OSCO) X1.2
NetC50_1: C50.1 U15.3(C1-)
NetC50_2: C50.2 U15.1(C1+)
NetC52_2: C52.2 U15.2(V+)
NetC53_1: C53.1 U15.5(C2-)
NetC53_2: C53.2 U15.4(C2+)
NetC54_2: C54.2 U15.6(V-)
NetC147_1: C147.1 U31.3(C1-)
NetC147_2: C147.2 U31.1(C1+)
NetC149_2: C149.2 U31.2(V+)
NetC150_1: C150.1 U31.5(C2-)
NetC150_2: C150.2 U31.4(C2+)
NetC151_2: C151.2 U31.6(V-)
NetR37_1: R37.1 U11.2(~{RE}) U11.3(~{SHDN})
NetR38_1: R38.1 U12.2(~{RE}) U12.3(~{SHDN})
NetR47_1: R47.1 U13.8(S)
NetR48_1: R48.1 U14.8(S)

Not connected (* = marked no-connect by the designer): COM3 1 4 6 7 8 9; COM4 1 4 6 7 8 9; U9 3(~{INT})* 7(CLKOUT); U15 7(TOUT2) 8(RIN2) 9(ROUT2) 10(TIN2); U31 7(TOUT2) 8(RIN2) 9(ROUT2) 10(TIN2)

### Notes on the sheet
- RS232_1
- RS232_2
- CAN&RS485 HEADER
- RS485_1
- RS485_2
- CAN1
- CAN0
- RTC
- (near D9) I2C Pull-up Resistor
- EEPROM
- SPI FLASH

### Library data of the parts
BAT = CR-3V: 微型电池; 版权归属: 正点原子
C37-C43 C46-C54 C147-C151 = C: 无极性贴片电容; 版权归属: 正点原子
COM3 COM4 = DB9: 9针串口; 版权归属: 正点原子
D6-D9 = HDW24M2T-B: ESD
J5 = KF2EDGR-3.81-8P: 弯脚,接线端子,8脚,间距3.81mm
R35 R36 R82 R152 = R: 电阻; BOM名称: 贴片电阻; 版权归属: 正点原子
R37-R50 R111 R114 = R: 贴片电阻; 版权归属: 正点原子
U8 = AT24CXX: 外置EEPROM
U9 = PCF8563
U10 = W25Q128JV: SPI FLASH
U11 U12 = COS13488EE: RS485 Auto-Direction Control
U13 U14 = TPT1051V: CAN/CANFD
U15 U31 = TPT3232E: RS232; BOM名称: RS232通讯芯片; 版权归属: 正点原子; Parameter: 芯片
VD5 = BAT54C: 肖特基二极管（双）
X1 = XTAL-2P: 2脚无源晶振; BOM名称: 2脚晶振; 版权归属: 正点原子; Parameter: 晶振

## Sheet 06_ATK-DLRK3562JB_4G_HUB.SchDoc
size A4; Author: ALIENTEK; Revision: 0; SheetNumber: 6; SheetTotal: 11; Version: V1.0; SheetSize: A4
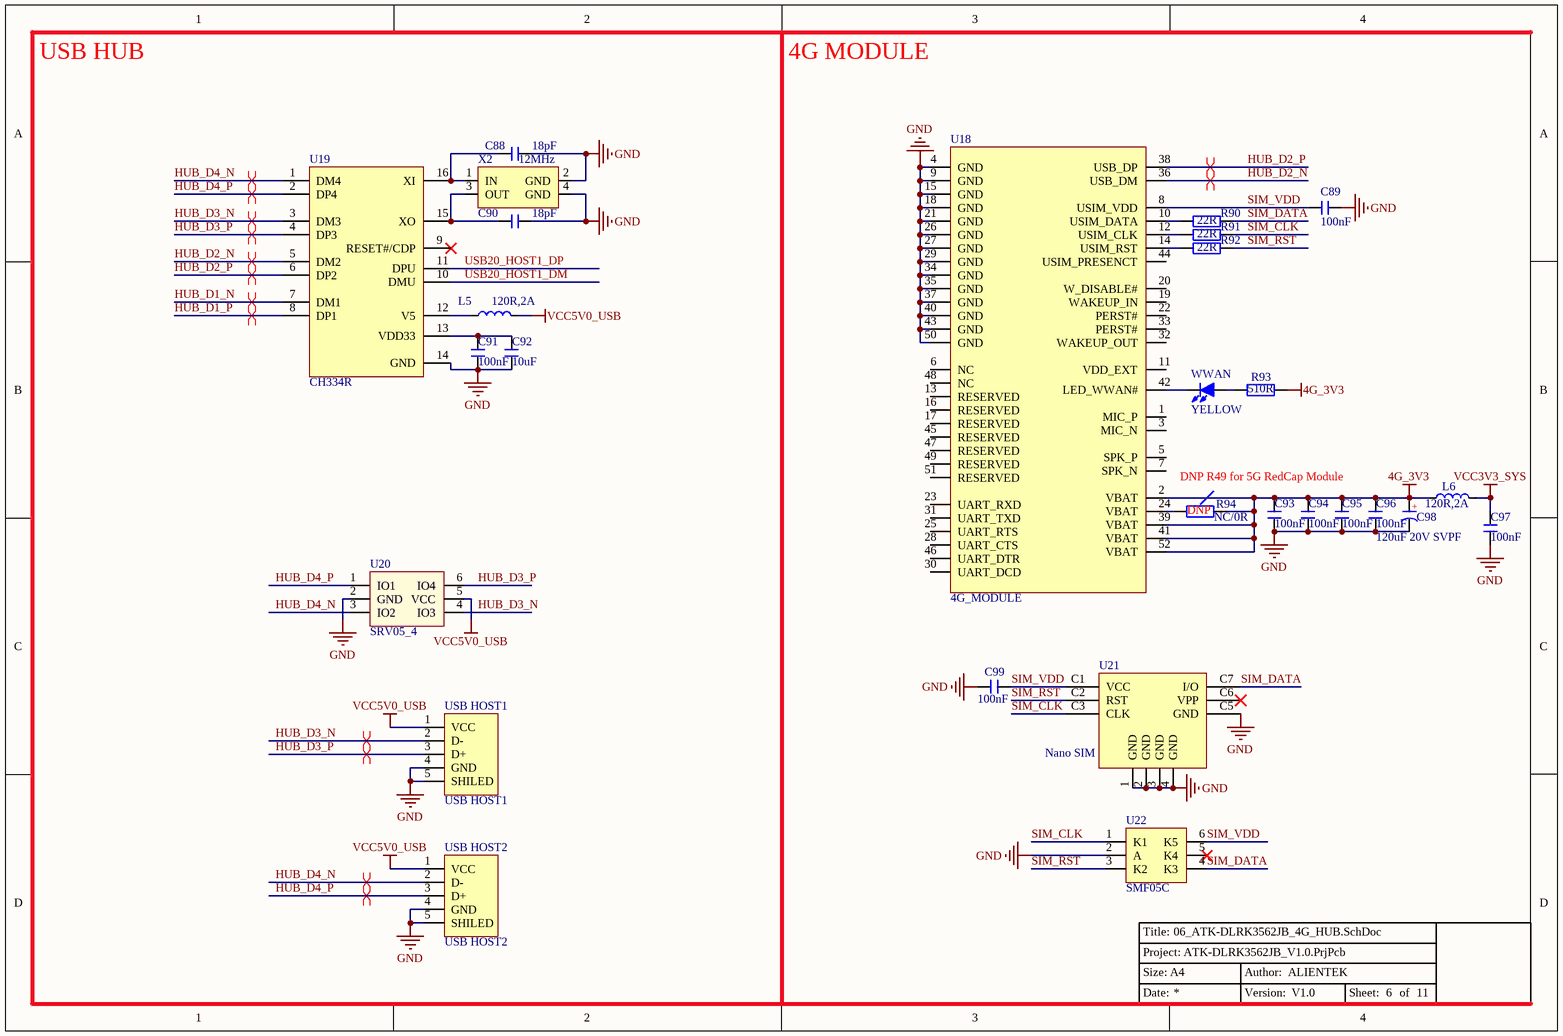
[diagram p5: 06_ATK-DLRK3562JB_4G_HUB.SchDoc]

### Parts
C88  18pF  [C 0402]
C89  100nF  [C 0402]
C90  18pF  [C 0402]
C91  100nF  [C 0402]
C92  10uF  [C 0805]
C93  100nF  [C 0402]
C94  100nF  [C 0402]
C95  100nF  [C 0402]
C96  100nF  [C 0402]
C97  100nF  [C 0402]
C98  120uF 20V SVPF  [CM D(6.3*7.7)]
C99  100nF  [C 0402]
L5  120R,2A  [L 0603]
L6  120R,2A  [L 0603]
R90  22R  [R 0402]
R91  22R  [R 0402]
R92  22R  [R 0402]
R93  510R  [R 0402]
R94  NC/0R  [R 0402]
U18  4G_MODULE  [Mini PCIE 52P]
U19  CH334R  [QSOP16]
U20  SRV05_4  [SOT23-6L]
U21  Nano SIM  [Nano SIM 7P]
U22  SMF05C  [SOT363-6N]
USB_HOST1  USB HOST1  [USB-A/S_E]
USB_HOST2  USB HOST2  [USB-A/S_E]
WWAN  YELLOW  [LED 0805 Yellow]
X2  12MHz  [XTAL-3225]

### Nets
4G_3V3: C93.2 C94.2 C95.2 C96.2 C98.1(A) L6.1 R93.2 R94.2 U18.2(VBAT) U18.39(VBAT) U18.41(VBAT) U18.52(VBAT)
GND: C88.2 C89.2 C90.2 C91.1 C92.1 C93.1 C94.1 C95.1 C96.1 C97.1 C98.2(K) C99.2 U18.4(GND) U18.9(GND) U18.15(GND) U18.18(GND) U18.21(GND) U18.26(GND) U18.27(GND) U18.29(GND) U18.34(GND) U18.35(GND) U18.37(GND) U18.40(GND) U18.43(GND) U18.50(GND) U19.14(GND) U20.2(GND) U21.1(GND) U21.2(GND) U21.3(GND) U21.4(GND) U21.C5(GND) U22.2(A) USB_HOST1.4(GND) USB_HOST1.5(SHILED) USB_HOST2.4(GND) USB_HOST2.5(SHILED) X2.2(GND) X2.4(GND)
VCC3V3_SYS: C97.2 L6.2
VCC5V0_USB: L5.2 U20.5(VCC) USB_HOST1.1(VCC) USB_HOST2.1(VCC)
HUB_D1_N: U19.7(DM1)
HUB_D1_P: U19.8(DP1)
HUB_D2_N: U18.36(USB_DM) U19.5(DM2)
HUB_D2_P: U18.38(USB_DP) U19.6(DP2)
HUB_D3_N: U19.3(DM3) U20.4(IO3) USB_HOST1.2(D-)
HUB_D3_P: U19.4(DP3) U20.6(IO4) USB_HOST1.3(D+)
HUB_D4_N: U19.1(DM4) U20.3(IO2) USB_HOST2.2(D-)
HUB_D4_P: U19.2(DP4) U20.1(IO1) USB_HOST2.3(D+)
SIM_CLK: R91.2 U21.C3(CLK) U22.1(K1)
SIM_DATA: R90.2 U21.C7(I/O) U22.4(K3)
SIM_RST: R92.2 U21.C2(RST) U22.3(K2)
SIM_VDD: C89.1 C99.1 U18.8(USIM_VDD) U21.C1(VCC) U22.6(K5)
USB20_HOST1_DM: U19.10(DMU)
USB20_HOST1_DP: U19.11(DPU)
NetC88_1: C88.1 U19.16(XI) X2.1(IN)
NetC90_1: C90.1 U19.15(XO) X2.3(OUT)
NetC91_2: C91.2 C92.2 U19.13(VDD33)
NetL5_1: L5.1 U19.12(V5)
NetR90_1: R90.1 U18.10(USIM_DATA)
NetR91_1: R91.1 U18.12(USIM_CLK)
NetR92_1: R92.1 U18.14(USIM_RST)
NetR93_1: R93.1 WWAN.1(A)
NetR94_1: R94.1 U18.24(VBAT)
NetU18_42: U18.42(LED_WWAN#) WWAN.2(K)

Not connected (* = marked no-connect by the designer): U18 1(MIC_P) 3(MIC_N) 5(SPK_P) 6(NC) 7(SPK_N) 11(VDD_EXT) 13(RESERVED) 16(RESERVED) 17(RESERVED) 19(WAKEUP_IN) 20(W_DISABLE#) 22(PERST#) 23(UART_RXD) 25(UART_RTS) 28(UART_CTS) 30(UART_DCD) 31(UART_TXD) 32(WAKEUP_OUT) 33(PERST#) 44(USIM_PRESENCT) 45(RESERVED) 46(UART_DTR) 47(RESERVED) 48(NC) 49(RESERVED) 51(RESERVED); U19 9(RESET#/CDP)*; U21 C4(NC) C6(VPP)*; U22 5(K4)*

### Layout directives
differential pair: HUB_D1_N, HUB_D1_P, HUB_D2_N, HUB_D2_P, HUB_D3_N, HUB_D3_P, HUB_D4_N, HUB_D4_P

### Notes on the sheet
- USB HUB
- 4G MODULE
- DNP R49 for 5G RedCap Module
- (near R94) DNP

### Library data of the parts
C88 C90-C92 = C: 无极性贴片电容; 版权归属: 源创客
C89 C93-C97 C99 = C: 无极性贴片电容; 版权归属: 正点原子
C98 = C-CM: 贴片电解电容; 版权归属: 源创客
L5 L6 = L: 小功率贴片电感磁珠; 版权归属: 正点原子
R90-R93 = R: 贴片电阻; 版权归属: 正点原子
R94 = R: 电阻; BOM名称: 贴片电阻; 版权归属: 正点原子
U18 = 4G-EC20
U20 = SRV05_4: ESD保护二极管阵列
U22 = SMF05C: 5线TVS管; 版权归属: 正点原子; Parameter: 芯片
USB_HOST1 USB_HOST2 = USB-A/S: USB-A型母接口; 版权归属: 源创客
WWAN = LED: as DS on sheet 03_ATK-DLRK3562JB_POWER_UART
X2 = XTAL-4P: 4脚无源晶振; BOM名称: 4脚晶振; 版权归属: 正点原子; Parameter: 晶振

## Sheet 07_ATK-DLRK3562JB_WIFI_TF_OTG_PINOUT.SchDoc
size A4; Author: ALIENTEK; Revision: 0; SheetNumber: 7; SheetTotal: 11; Version: V1.0; SheetSize: A4
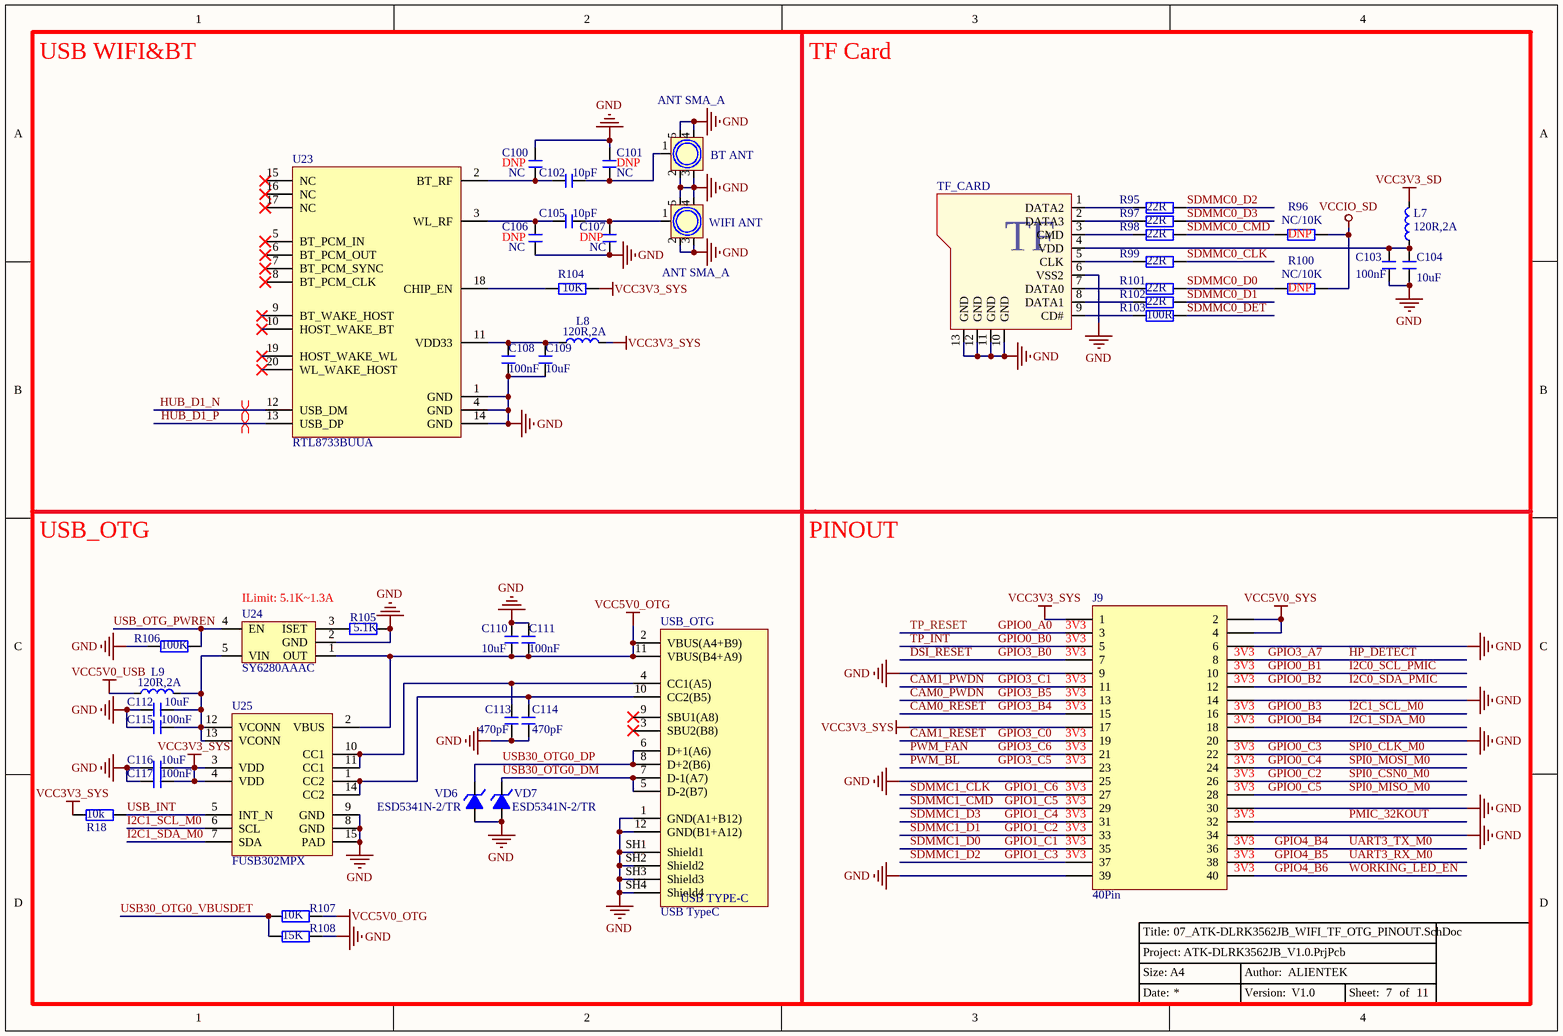
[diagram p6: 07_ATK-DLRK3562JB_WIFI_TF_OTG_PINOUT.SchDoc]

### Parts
BT_ANT  ANT SMA_A  [SMA-KWE]
C100  NC  [C 0402]
C101  NC  [C 0402]
C102  10pF  [C 0402]
C103  100nF  [C 0402]
C104  10uF  [C 0805]
C105  10pF  [C 0402]
C106  NC  [C 0402]
C107  NC  [C 0402]
C108  100nF  [C 0402]
C109  10uF  [C 0805]
C110  10uF  [C 0805]
C111  100nF  [C 0402]
C112  10uF  [C 0805]
C113  470pF  [C 0402]
C114  470pF  [C 0402]
C115  100nF  [C 0402]
C116  10uF  [C 0805]
C117  100nF  [C 0402]
J9  40Pin  [HDR-20X2]
L7  120R,2A  [L 0603]
L8  120R,2A  [L 0603]
L9  120R,2A  [L 0603]
R18  10k  [R 0402]
R95  22R  [R 0402]
R96  NC/10K  [R 0402]
R97  22R  [R 0402]
R98  22R  [R 0402]
R99  22R  [R 0402]
R100  NC/10K  [R 0402]
R101  22R  [R 0402]
R102  22R  [R 0402]
R103  100R  [R 0402]
R104  10K  [R 0402]
R105  5.1K  [R 0402]
R106  100K  [R 0402]
R107  10K  [R 0402]
R108  15K  [R 0402]
TF_CARD  SD-MICRO-TF  [SD-MICRO-TF]  (value not drawn)
U23  RTL8733BUUA  [RTL8733BUBUA]
U24  SY6280AAAC  [SOT23-5N]
U25  FUSB302MPX  [MLP14]
USB_OTG  USB TypeC  [USB2.0-TYPE-C-16P]
VD6  ESD5341N-2/TR  [ESD0402]
VD7  ESD5341N-2/TR  [ESD0402]
WIFI_ANT  ANT SMA_A  [SMA-KWE]

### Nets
GND: BT_ANT.2(GND) BT_ANT.3(GND) BT_ANT.4 BT_ANT.5 C100.1 C101.1 C103.2 C104.1 C106.2 C107.2 C108.2 C109.2 C110.1 C111.1 C112.1 C113.2 C114.1 C115.1 C116.1 C117.1 J9.6 J9.9 J9.14 J9.20 J9.25 J9.30 J9.34 J9.39 R105.2 R106.1 R108.2 TF_CARD.6(VSS2) TF_CARD.10(GND) TF_CARD.11(GND) TF_CARD.12(GND) TF_CARD.13(GND) U23.1(GND) U23.4(GND) U23.14(GND) U24.2(GND) U25.8(GND) U25.9(GND) U25.15(PAD) USB_OTG.1(GND(A1+B12)) USB_OTG.12(GND(B1+A12)) USB_OTG.SH1(Shield1) USB_OTG.SH2(Shield2) USB_OTG.SH3(Shield3) USB_OTG.SH4(Shield4) VD6.2 VD7.2 WIFI_ANT.2(GND) WIFI_ANT.3(GND) WIFI_ANT.4 WIFI_ANT.5
VCC3V3_SD: L7.2
VCC3V3_SYS: C116.2 C117.2 J9.1 J9.17 L8.2 R18.1 R104.1 U25.3(VDD) U25.4(VDD)
VCC5V0_OTG: C110.2 C111.2 R107.2 U24.1(OUT) U25.2(VBUS) USB_OTG.2(VBUS(A4+B9)) USB_OTG.11(VBUS(B4+A9))
VCC5V0_SYS: J9.2 J9.4
VCC5V0_USB: L9.1
VCCIO_SD: R96.1 R100.1
CAM0_PWDN: J9.13  [also labelled GPIO3_B5]
CAM0_RESET: J9.15  [also labelled GPIO3_B4]
CAM1_PWDN: J9.11  [also labelled GPIO3_C1]
CAM1_RESET: J9.19  [also labelled GPIO3_C0]
DSI_RESET: J9.7  [also labelled GPIO3_B0]
GPIO0_A0: J9.3  [also labelled TP_RESET]
GPIO0_B0: J9.5  [also labelled TP_INT]
GPIO0_B1: J9.10  [also labelled I2C0_SCL_PMIC]
GPIO0_B2: J9.12  [also labelled I2C0_SDA_PMIC]
GPIO0_B3: J9.16 U25.6(SCL)  [also labelled I2C1_SCL_M0]
GPIO0_B4: J9.18 U25.7(SDA)  [also labelled I2C1_SDA_M0]
GPIO0_C2: J9.26  [also labelled SPI0_CSN0_M0]
GPIO0_C3: J9.22  [also labelled SPI0_CLK_M0]
GPIO0_C4: J9.24  [also labelled SPI0_MOSI_M0]
GPIO0_C5: J9.28  [also labelled SPI0_MISO_M0]
GPIO1_C1: J9.35  [also labelled SDMMC1_D0]
GPIO1_C2: J9.33  [also labelled SDMMC1_D1]
GPIO1_C3: J9.37  [also labelled SDMMC1_D2]
GPIO1_C4: J9.31  [also labelled SDMMC1_D3]
GPIO1_C5: J9.29  [also labelled SDMMC1_CMD]
GPIO1_C6: J9.27  [also labelled SDMMC1_CLK]
GPIO3_A7: J9.8  [also labelled HP_DETECT]
GPIO3_C5: J9.23  [also labelled PWM_BL]
GPIO3_C6: J9.21  [also labelled PWM_FAN]
GPIO4_B4: J9.36  [also labelled UART3_TX_M0]
GPIO4_B5: J9.38  [also labelled UART3_RX_M0]
GPIO4_B6: J9.40  [also labelled WORKING_LED_EN]
HUB_D1_N: U23.12(USB_DM)
HUB_D1_P: U23.13(USB_DP)
PMIC_32KOUT: J9.32
SDMMC0_CLK: R99.2  [project net GPIO1_C0]
SDMMC0_CMD: R96.2 R98.2  [project net GPIO1_B7]
SDMMC0_D0: R100.2 R101.2  [project net GPIO1_B3]
SDMMC0_D1: R102.2  [project net GPIO1_B4]
SDMMC0_D2: R95.2  [project net GPIO1_B5]
SDMMC0_D3: R97.2  [project net GPIO1_B6]
SDMMC0_DET: R103.2  [project net GPIO0_A4]
USB30_OTG0_DM: USB_OTG.5(D-2(B7)) USB_OTG.7(D-1(A7)) VD7.1
USB30_OTG0_DP: USB_OTG.6(D+1(A6)) USB_OTG.8(D+2(B6)) VD6.1
USB30_OTG0_VBUSDET: R107.1 R108.1
USB_INT: R18.2 U25.5(INT_N)  [project net GPIO3_A1]
USB_OTG_PWREN: R106.2 U24.4(EN)  [project net GPIO3_A0]
NetBT_ANT_1: BT_ANT.1(ANT) C101.2 C102.1
NetC100_2: C100.2 C102.2 U23.2(BT_RF)
NetC103_1: C103.1 C104.2 L7.1 TF_CARD.4(VDD)
NetC105_1: C105.1 C107.1 WIFI_ANT.1(ANT)
NetC105_2: C105.2 C106.1 U23.3(WL_RF)
NetC108_1: C108.1 C109.1 L8.1 U23.11(VDD33)
NetC112_2: C112.2 C115.2 L9.2 U24.5(VIN) U25.12(VCONN) U25.13(VCONN)
NetC113_1: C113.1 U25.10(CC1) U25.11(CC1) USB_OTG.4(CC1(A5))
NetC114_2: C114.2 U25.1(CC2) U25.14(CC2) USB_OTG.10(CC2(B5))
NetR95_1: R95.1 TF_CARD.1(DATA2)
NetR97_1: R97.1 TF_CARD.2(DATA3)
NetR98_1: R98.1 TF_CARD.3(CMD)
NetR99_1: R99.1 TF_CARD.5(CLK)
NetR101_1: R101.1 TF_CARD.7(DATA0)
NetR102_1: R102.1 TF_CARD.8(DATA1)
NetR103_1: R103.1 TF_CARD.9(CD#)
NetR104_2: R104.2 U23.18(CHIP_EN)
NetR105_1: R105.1 U24.3(ISET)

Not connected (* = marked no-connect by the designer): U23 5(BT_PCM_IN)* 6(BT_PCM_OUT)* 7(BT_PCM_SYNC)* 8(BT_PCM_CLK)* 9(BT_WAKE_HOST)* 10(HOST_WAKE_BT)* 15(NC)* 16(NC)* 17(NC)* 19(HOST_WAKE_WL)* 20(WL_WAKE_HOST)*; USB_OTG 3(SBU2(B8))* 9(SBU1(A8))*

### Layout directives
differential pair: HUB_D1_N, HUB_D1_P

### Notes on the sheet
- USB WIFI&BT
- TF Card
- (near C100) DNP
- (near C101) DNP
- (near C106) DNP
- DNP
- (near R96) DNP
- (near R100) DNP
- USB_OTG
- PINOUT
- ILimit: 5.1K
  .3A
- (near J9) 3V3

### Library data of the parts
BT_ANT WIFI_ANT = ANT SMA_A: SMA-射频接口; BOM名称: SMA-2.4G射频天线接口; 版权归属: 正点原子; Parameter: 接口器件
C100-C102 C105-C109 = C: 无极性贴片电容; 版权归属: 源创客
C103 C104 C110-C117 = C: 无极性贴片电容; 版权归属: 正点原子
J9 = RPI40Pin
L7-L9 = L: 小功率贴片电感磁珠; 版权归属: 正点原子
R18 R95 R97-R99 R101-R103 R106-R108 = R: 电阻; BOM名称: 贴片电阻; 版权归属: 正点原子
R96 R100 R104 R105 = R: 贴片电阻; 版权归属: 正点原子
TF_CARD = SD-MICRO-TF: SD,MICRO,TF
U24 = MT9700HT5: 功率开关(5.5V-2A); BOM名称: 稳压芯片; 版权归属: 正点原子
U25 = FUSB302MPX: USB Type-C 控制器
USB_OTG = USB Type-C: 12P TypeC 母座
VD6 VD7 = ESD5341N: ESD二极管-单向

## Sheet 08_ATK-DLRK3562JB_PCIE_AUDIO.SchDoc
size A4; Author: ALIENTEK; Revision: 0; SheetNumber: 8; SheetTotal: 11; Version: V1.0; SheetSize: A4
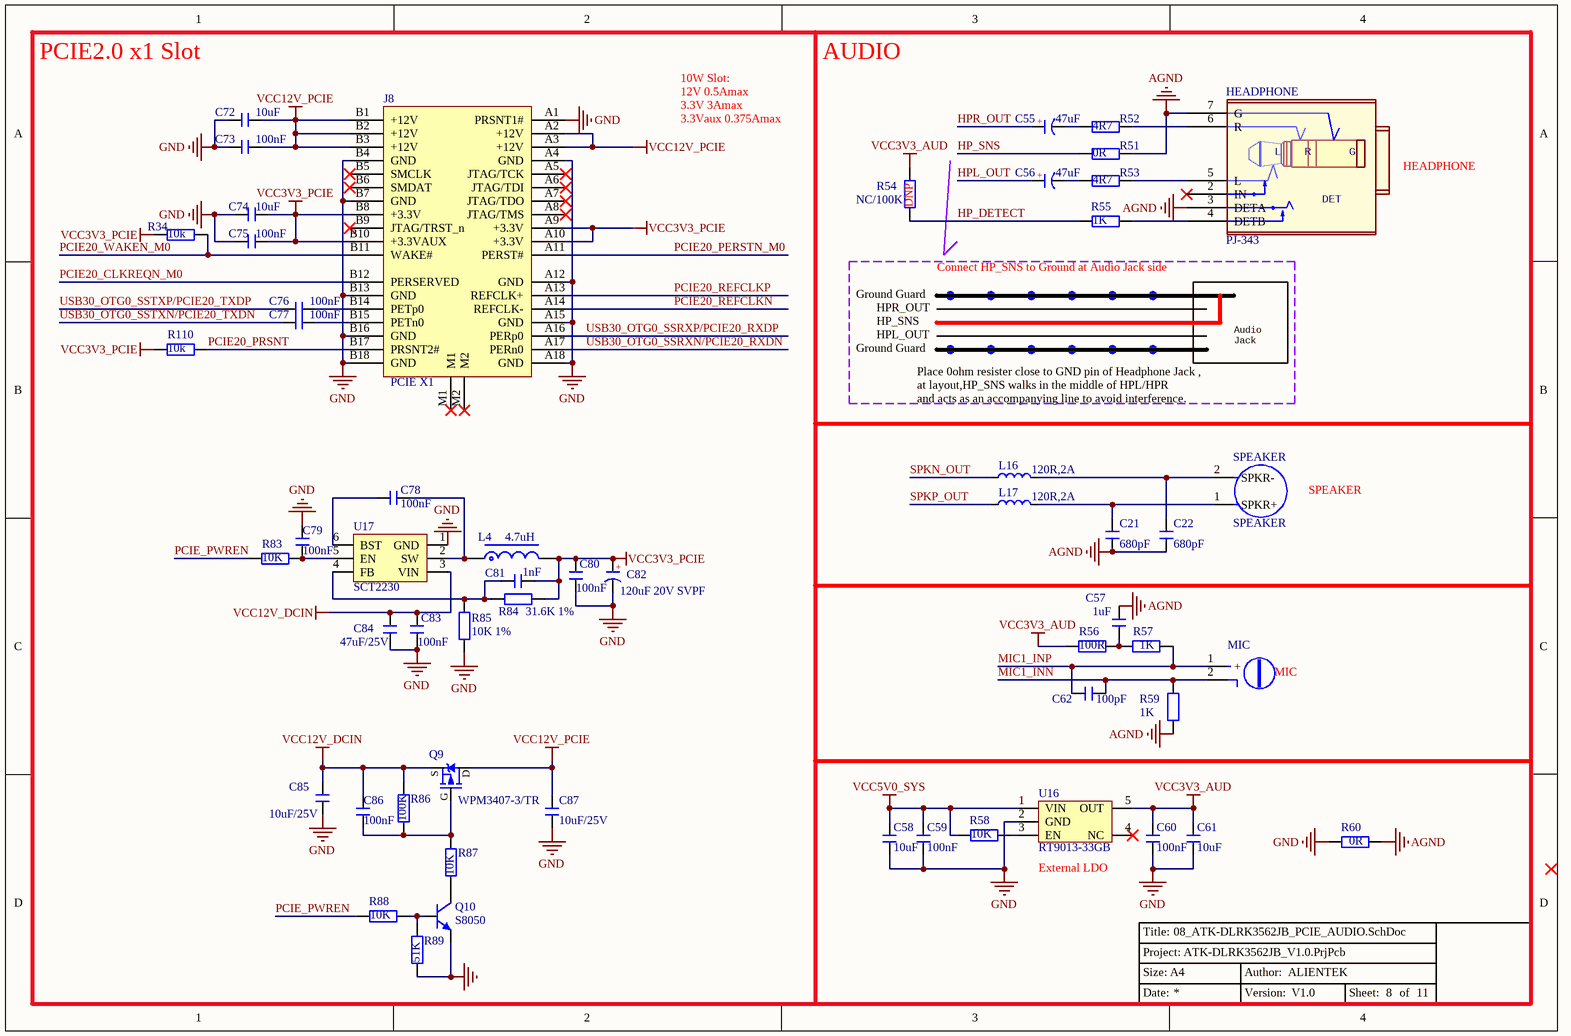
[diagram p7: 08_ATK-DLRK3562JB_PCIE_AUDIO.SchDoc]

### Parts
C21  680pF  [C 0402]
C22  680pF  [C 0402]
C55  47uF  [CM B(4*5.4)]
C56  47uF  [CM B(4*5.4)]
C57  1uF  [C 0603]
C58  10uF  [C 0805]
C59  100nF  [C 0402]
C60  100nF  [C 0402]
C61  10uF  [C 0805]
C62  100pF  [C 0402]
C72  10uF  [C 0805]
C73  100nF  [C 0402]
C74  10uF  [C 0805]
C75  100nF  [C 0402]
C76  100nF  [C 0402]
C77  100nF  [C 0402]
C78  100nF  [C 0402]
C79  100nF  [C 0402]
C80  100nF  [C 0402]
C81  1nF  [C 0402]
C82  120uF 20V SVPF  [CM D(6.3*7.7)]
C83  100nF  [C 0402]
C84  47uF/25V  [C 1206]
C85  10uF/25V  [C 0805]
C86  100nF  [C 0402]
C87  10uF/25V  [C 0805]
HEADPHONE  PJ-343  [PJ-343]
J8  PCIE X1  [PCIEX1]
L4  4.7uH  [L-SMD-0420]
L16  120R,2A  [L 0603]
L17  120R,2A  [L 0603]
MIC  MIC-6022  [MIC-6022]  (value not drawn)
Q9  WPM3407-3/TR  [SOT23-3N]
Q10  S8050  [SOT23-3N]
R34  10k  [R 0402]
R51  0R  [R 0402]
R52  4R7  [R 0402]
R53  4R7  [R 0402]
R54  NC/100K  [R 0402]
R55  1K  [R 0402]
R56  100R  [R 0402]
R57  1K  [R 0402]
R58  10K  [R 0402]
R59  1K  [R 0402]
R60  0R  [R 0402]
R83  10K  [R 0402]
R84  31.6K 1%  [R 0402]
R85  10K 1%  [R 0402]
R86  100K  [R 0402]
R87  10K  [R 0402]
R88  10K  [R 0402]
R89  51K  [R 0402]
R110  10k  [R 0402]
SPEAKER  SPEAKER  [SPEAKER]
U16  RT9013-33GB  [SOT23-5N]
U17  SCT2230  [SOT23-6N]

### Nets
AGND: C21.1 C22.1 C57.2 HEADPHONE.3(DETA) HEADPHONE.7(G) R51.1 R59.1 R60.2
GND: C58.1 C59.1 C60.1 C61.1 C72.2 C73.2 C74.2 C75.1 C79.2 C80.2 C82.2(K) C83.1 C84.1 C85.1 C87.1 J8.A1(PRSNT1#) J8.A4(GND) J8.A12(GND) J8.A15(GND) J8.A18(GND) J8.B4(GND) J8.B7(GND) J8.B13(GND) J8.B16(GND) J8.B18(GND) Q10.2(E) R60.1 R85.2 R89.1 U16.2(GND) U17.1(GND)
VCC3V3_AUD: C60.2 C61.2 R54.2 R56.1 U16.5(OUT)
VCC3V3_PCIE: C74.1 C75.2 C80.1 C81.1 C82.1(A) J8.A9(+3.3V) J8.A10(+3.3V) J8.B8(+3.3V) J8.B10(+3.3VAUX) L4.2 R34.1 R84.2 R110.1
VCC5V0_SYS: C58.2 C59.2 R58.1 U16.1(VIN)
VCC12V_DCIN: C83.2 C84.2 C85.2 C86.2 Q9.2(S) R86.2 U17.3(VIN)
VCC12V_PCIE: C72.1 C73.1 C87.2 J8.A2(+12V) J8.A3(+12V) J8.B1(+12V) J8.B2(+12V) J8.B3(+12V) Q9.3(D)
HP_DETECT: R54.1 R55.2  [project net GPIO3_A7]
HP_SNS: R51.2
HPL_OUT: C56.1(A)
HPR_OUT: C55.1(A)
MIC1_INN: C62.2 MIC.2(GND) R59.2
MIC1_INP: C62.1 MIC.1(+) R57.2
PCIE20_CLKREQN_M0: J8.B12(PERSERVED)  [project net GPIO0_A6]
PCIE20_PERSTN_M0: J8.A11(PERST#)  [project net GPIO0_B5]
PCIE20_PRSNT: J8.B17(PRSNT2#) R110.2  [project net GPIO0_A5]
PCIE20_REFCLKN: J8.A14(REFCLK-)
PCIE20_REFCLKP: J8.A13(REFCLK+)
PCIE20_WAKEN_M0: J8.B11(WAKE#) R34.2  [project net GPIO0_B6]
PCIE_PWREN: R83.1 R88.2  [project net GPIO0_B7]
SPKN_OUT: L16.1
SPKP_OUT: L17.1
USB30_OTG0_SSRXN/PCIE20_RXDN: J8.A17(PERn0)
USB30_OTG0_SSRXP/PCIE20_RXDP: J8.A16(PERp0)
USB30_OTG0_SSTXN/PCIE20_TXDN: C77.1
USB30_OTG0_SSTXP/PCIE20_TXDP: C76.1
NetC21_2: C21.2 L17.2 SPEAKER.1(SPKR+)
NetC22_2: C22.2 L16.2 SPEAKER.2(SPKR-)
NetC55_2: C55.2(K) R52.2
NetC56_2: C56.2(K) R53.2
NetC57_1: C57.1 R56.2 R57.1
NetC76_2: C76.2 J8.B14(PETp0)
NetC77_2: C77.2 J8.B15(PETn0)
NetC78_1: C78.1 U17.6(BST)
NetC78_2: C78.2 L4.1 U17.2(SW)
NetC79_1: C79.1 R83.2 U17.5(EN)
NetC81_2: C81.2 R84.1 R85.1 U17.4(FB)
NetC86_1: C86.1 Q9.1(G) R86.1 R87.2
NetHEADPHONE_4: HEADPHONE.4(DETB) R55.1
NetHEADPHONE_5: HEADPHONE.5(L) R53.1
NetHEADPHONE_6: HEADPHONE.6(R) R52.1
NetQ10_1: Q10.1(B) R88.1 R89.2
NetQ10_3: Q10.3(C) R87.1
NetR58_2: R58.2 U16.3(EN)

Not connected (* = marked no-connect by the designer): HEADPHONE 2(IN)*; J8 A5(JTAG/TCK)* A6(JTAG/TDI)* A7(JTAG/TDO)* A8(JTAG/TMS)* B5(SMCLK)* B6(SMDAT)* B9(JTAG/TRST_n)* M1* M2*; U16 4(NC)*

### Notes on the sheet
- PCIE2.0 x1 Slot
- 10W Slot:
- 12V 0.5Amax
- 3.3V 3Amax
- AUDIO
- 3.3Vaux 0.375Amax
- HEADPHONE
- (near R54) DNP
- Ground Guard
- HPR_OUT
- Connect HP_SNS to Ground at Audio Jack side
- HPL_OUT
- HP_SNS
- Audio
  Jack
- Place 0ohm resister close to GND pin of Headphone Jack ,
  at layout,HP_SNS walks in the middle of HPL/HPR
  and acts as an accompanying line to avoid interference.
- SPEAKER
- (near MIC) MIC
- (near U16) External LDO

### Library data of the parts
C21 C22 C57 C72 C76 C77 C85-C87 = C: 无极性电容; BOM名称: 无极性贴片电容; 版权归属: 正点原子
C55 C56 C82 = C-CM: 贴片电解电容; 版权归属: 源创客
C58-C62 C73-C75 C78-C81 C83 C84 = C: 无极性贴片电容; 版权归属: 源创客
J8 = PCIEX1: PCIE连接座36P
L4 = L-CDRH: 功率屏蔽电感; 版权归属: 源创客
L16 L17 = FB: 贴片磁珠; BOM名称: 小功率贴片电感; 版权归属: 正点原子; Parameter: 电感/磁珠
MIC = MIC-6022: MIC; 版权归属: 正点原子; Parameter: 接口器件
Q9 = PMOS: BOM名称: P沟道场效应管; 版权归属: 正点原子; Parameter: MOS管
Q10 = 8050-SMD: as Q2 on sheet 03_ATK-DLRK3562JB_POWER_UART
R34 R51-R57 R59 R60 R86-R89 R110 = R: 电阻; BOM名称: 贴片电阻; 版权归属: 正点原子
R58 = R: 贴片电阻; BOM名称: 电阻; 版权归属: 正点原子
R83-R85 = R: 贴片电阻; 版权归属: 源创客
SPEAKER = SPEAKER: 喇叭2307
U16 = RT9013: LDO 5.5V 500mA; BOM名称: 稳压芯片; 版权归属: 正点原子; Parameter: 芯片
U17 = DC JW5060T_6: DC降压芯片

## Sheet 09_ATK-DLRK3562JB_LCD_CAMERA.SchDoc
size A4; Author: ALIENTEK; Revision: 0; SheetNumber: 9; SheetTotal: 11; Version: V1.0; SheetSize: A4
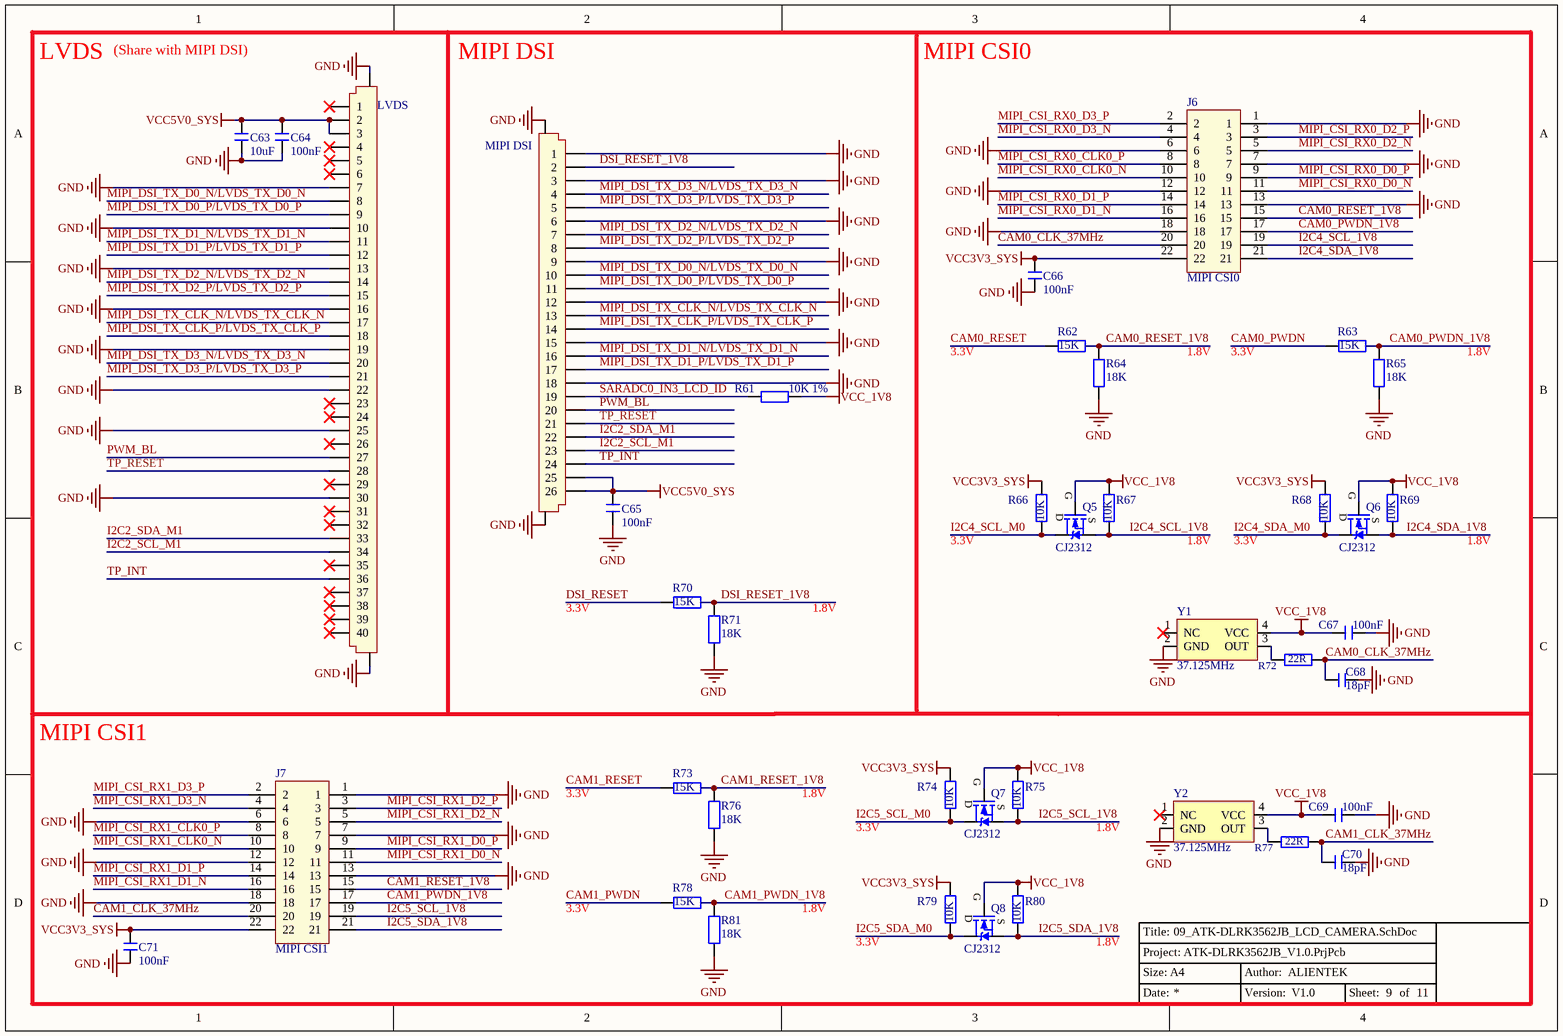
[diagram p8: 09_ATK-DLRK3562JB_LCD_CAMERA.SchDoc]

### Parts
C63  10uF  [C 0805]
C64  100nF  [C 0402]
C65  100nF  [C 0402]
C66  100nF  [C 0402]
C67  100nF  [C 0402]
C68  18pF  [C 0402]
C69  100nF  [C 0402]
C70  18pF  [C 0402]
C71  100nF  [C 0402]
J6  MIPI CSI0  [HEADER 2.0 2X11P]
J7  MIPI CSI1  [HEADER 2.0 2X11P]
LVDS  FPC0.5-40P  [FPC 0.5 40P V-S]  (value not drawn)
MIPI_DSI  FPC0.5-26P  [FPC 0.5 26P H-S]  (value not drawn)
Q5  CJ2312  [SOT23-3N]
Q6  CJ2312  [SOT23-3N]
Q7  CJ2312  [SOT23-3N]
Q8  CJ2312  [SOT23-3N]
R61  10K 1%  [R 0402]
R62  15K  [R 0402]
R63  15K  [R 0402]
R64  18K  [R 0402]
R65  18K  [R 0402]
R66  10K  [R 0402]
R67  10K  [R 0402]
R68  10K  [R 0402]
R69  10K  [R 0402]
R70  15K  [R 0402]
R71  18K  [R 0402]
R72  22R  [R 0402]
R73  15K  [R 0402]
R74  10K  [R 0402]
R75  10K  [R 0402]
R76  18K  [R 0402]
R77  22R  [R 0402]
R78  15K  [R 0402]
R79  10K  [R 0402]
R80  10K  [R 0402]
R81  18K  [R 0402]
Y1  37.125MHz  [XTAL-3225 - S]
Y2  37.125MHz  [XTAL-3225 - S]

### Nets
GND: C63.2 C64.2 C65.2 C66.1 C67.1 C68.2 C69.1 C70.2 C71.1 J6.1 J6.6 J6.7 J6.12 J6.13 J6.18 J7.1 J7.6 J7.7 J7.12 J7.13 J7.18 LVDS.0 LVDS.7 LVDS.10 LVDS.13 LVDS.16 LVDS.19 LVDS.22 LVDS.25 LVDS.30 MIPI_DSI.0 MIPI_DSI.1 MIPI_DSI.3 MIPI_DSI.6 MIPI_DSI.9 MIPI_DSI.12 MIPI_DSI.15 MIPI_DSI.18 R64.1 R65.1 R71.1 R76.1 R81.1 Y1.2(GND) Y2.2(GND)
VCC3V3_SYS: C66.2 C71.2 J6.22 J7.22 R66.2 R68.2 R74.2 R79.2
VCC5V0_SYS: C63.1 C64.1 C65.1 LVDS.2 LVDS.3 MIPI_DSI.25 MIPI_DSI.26
VCC_1V8: C67.2 C69.2 Q5.1(G) Q6.1(G) Q7.1(G) Q8.1(G) R61.2 R67.2 R69.2 R75.2 R80.2 Y1.4(VCC) Y2.4(VCC)
CAM0_CLK_37MHz: C68.1 J6.20 R72.1
CAM0_PWDN: R63.1
CAM0_PWDN_1V8: J6.17 R63.2 R65.2
CAM0_RESET: R62.1
CAM0_RESET_1V8: J6.15 R62.2 R64.2
CAM1_CLK_37MHz: C70.1 J7.20 R77.1
CAM1_PWDN: R78.1
CAM1_PWDN_1V8: J7.17 R78.2 R81.2
CAM1_RESET: R73.1
CAM1_RESET_1V8: J7.15 R73.2 R76.2
DSI_RESET: R70.1
DSI_RESET_1V8: MIPI_DSI.2 R70.2 R71.2
I2C2_SCL_M1: LVDS.34 MIPI_DSI.23  [project net GPIO3_D2]
I2C2_SDA_M1: LVDS.33 MIPI_DSI.22  [project net GPIO3_D3]
I2C4_SCL_1V8: J6.19 Q5.2(S) R67.1
I2C4_SCL_M0: Q5.3(D) R66.1  [project net GPIO3_B6]
I2C4_SDA_1V8: J6.21 Q6.2(S) R69.1
I2C4_SDA_M0: Q6.3(D) R68.1  [project net GPIO3_B7]
I2C5_SCL_1V8: J7.19 Q7.2(S) R75.1
I2C5_SCL_M0: Q7.3(D) R74.1  [project net GPIO3_C2]
I2C5_SDA_1V8: J7.21 Q8.2(S) R80.1
I2C5_SDA_M0: Q8.3(D) R79.1  [project net GPIO3_C3]
MIPI_CSI_RX0_CLK0_N: J6.10
MIPI_CSI_RX0_CLK0_P: J6.8
MIPI_CSI_RX0_D0_N: J6.11
MIPI_CSI_RX0_D0_P: J6.9
MIPI_CSI_RX0_D1_N: J6.16
MIPI_CSI_RX0_D1_P: J6.14
MIPI_CSI_RX0_D2_N: J6.5
MIPI_CSI_RX0_D2_P: J6.3
MIPI_CSI_RX0_D3_N: J6.4
MIPI_CSI_RX0_D3_P: J6.2
MIPI_CSI_RX1_CLK0_N: J7.10
MIPI_CSI_RX1_CLK0_P: J7.8
MIPI_CSI_RX1_D0_N: J7.11
MIPI_CSI_RX1_D0_P: J7.9
MIPI_CSI_RX1_D1_N: J7.16
MIPI_CSI_RX1_D1_P: J7.14
MIPI_CSI_RX1_D2_N: J7.5
MIPI_CSI_RX1_D2_P: J7.3
MIPI_CSI_RX1_D3_N: J7.4
MIPI_CSI_RX1_D3_P: J7.2
MIPI_DSI_TX_CLK_N/LVDS_TX_CLK_N: LVDS.17 MIPI_DSI.13
MIPI_DSI_TX_CLK_P/LVDS_TX_CLK_P: LVDS.18 MIPI_DSI.14
MIPI_DSI_TX_D0_N/LVDS_TX_D0_N: LVDS.8 MIPI_DSI.10
MIPI_DSI_TX_D0_P/LVDS_TX_D0_P: LVDS.9 MIPI_DSI.11
MIPI_DSI_TX_D1_N/LVDS_TX_D1_N: LVDS.11 MIPI_DSI.16
MIPI_DSI_TX_D1_P/LVDS_TX_D1_P: LVDS.12 MIPI_DSI.17
MIPI_DSI_TX_D2_N/LVDS_TX_D2_N: LVDS.14 MIPI_DSI.7
MIPI_DSI_TX_D2_P/LVDS_TX_D2_P: LVDS.15 MIPI_DSI.8
MIPI_DSI_TX_D3_N/LVDS_TX_D3_N: LVDS.20 MIPI_DSI.4
MIPI_DSI_TX_D3_P/LVDS_TX_D3_P: LVDS.21 MIPI_DSI.5
PWM_BL: LVDS.27 MIPI_DSI.20  [project net GPIO3_C5]
SARADC0_IN3_LCD_ID: MIPI_DSI.19 R61.1
TP_INT: LVDS.36 MIPI_DSI.24  [project net GPIO0_B0]
TP_RESET: LVDS.28 MIPI_DSI.21  [project net GPIO0_A0]
NetR72_2: R72.2 Y1.3(OUT)
NetR77_2: R77.2 Y2.3(OUT)

Not connected (* = marked no-connect by the designer): LVDS 1* 4* 5* 6* 23* 24* 26* 29* 31* 32* 35* 37* 38* 39* 40*; Y1 1(NC)*; Y2 1(NC)*

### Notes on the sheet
- LVDS
- (Share with MIPI DSI)
- MIPI DSI
- MIPI CSI0
- 3.3V
- 1.8V
- MIPI CSI1

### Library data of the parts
C63-C66 C68 C70 C71 = C: 无极性贴片电容; 版权归属: 正点原子
C67 C69 = C: 无极性电容; BOM名称: 无极性贴片电容; 版权归属: 正点原子
J6 J7 = HEADER 2X11P: 摄像头IMX335
LVDS = FPC-40P: FPC连接器; 版权归属: 正点原子; Parameter: 接口器件
MIPI_DSI = FPC-26P: FPC连接器
Q5-Q8 = SI2302: NMOS 20V-+5.0A 55mΩ; BOM名称: N沟道场效应管; 版权归属: 正点原子; Parameter: MOS管
R61-R71 R73-R76 R78-R81 = R: 电阻; BOM名称: 贴片电阻; 版权归属: 正点原子
R72 R77 = R: 贴片电阻; 版权归属: 源创客
Y1 Y2 = XTAL-4P_S: 4脚有源晶振; BOM名称: 4脚晶振; 版权归属: 正点原子; Parameter: 晶振

## Sheet 10_ATK-DLRK3562JB_RMII_NET.SchDoc
size A4; Author: ALIENTEK; Revision: 0; SheetNumber: 10; SheetTotal: 11; Version: V1.0; SheetSize: A4
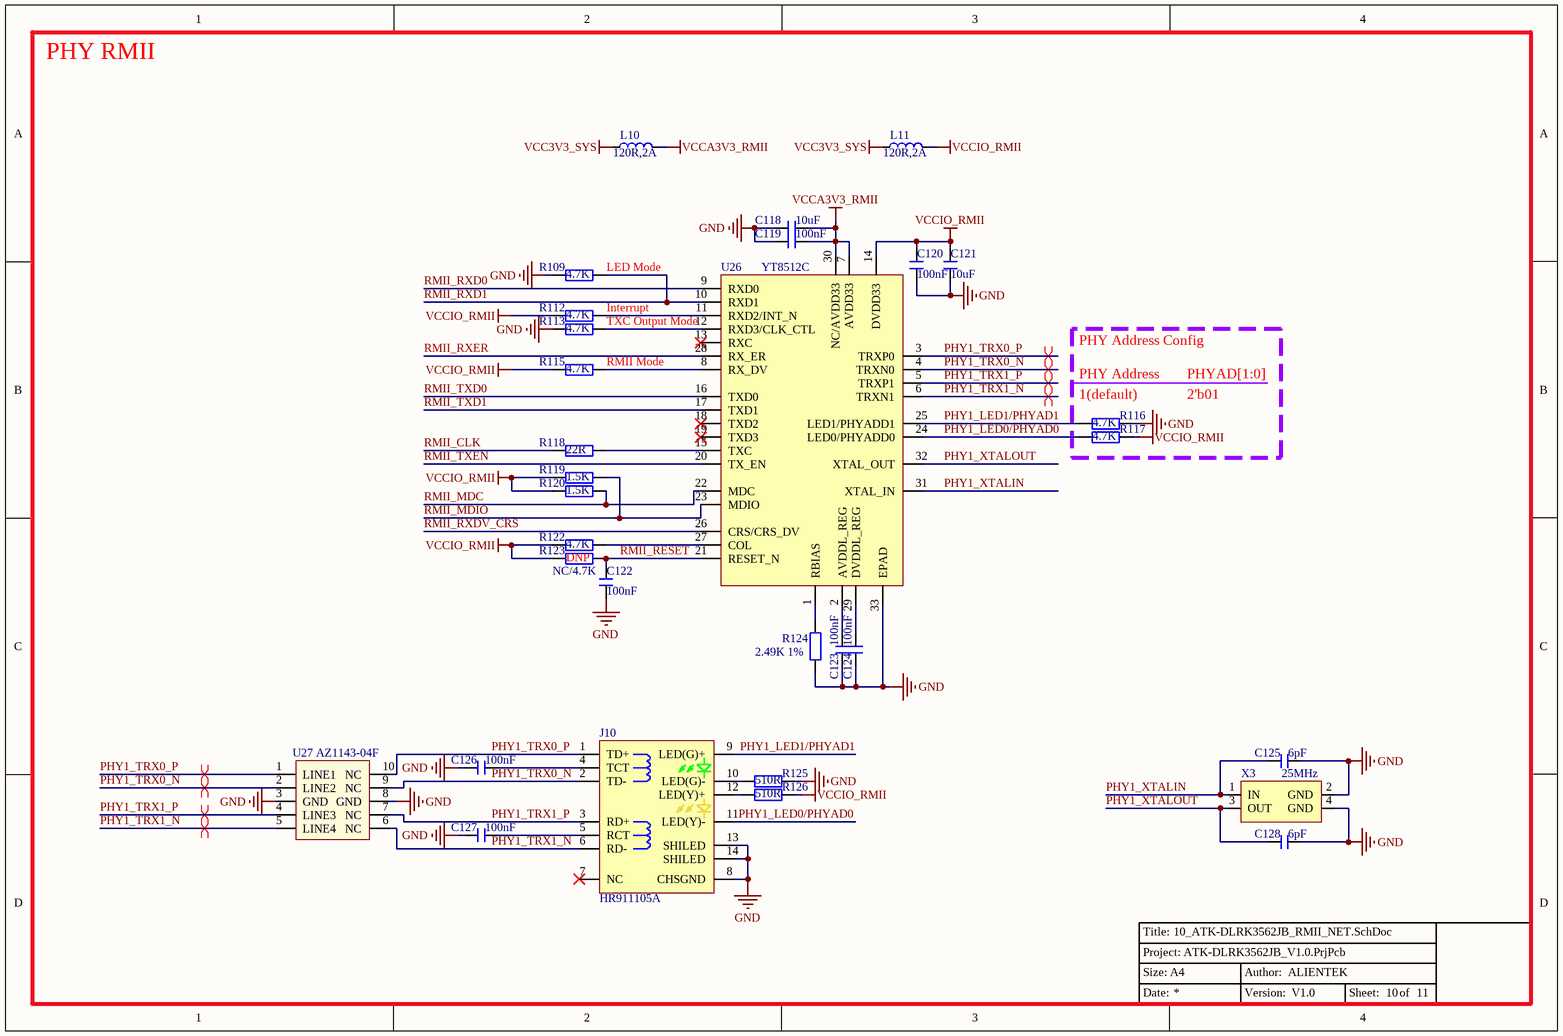
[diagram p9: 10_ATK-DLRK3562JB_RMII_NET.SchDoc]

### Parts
C118  10uF  [C 0805]
C119  100nF  [C 0402]
C120  100nF  [C 0402]
C121  10uF  [C 0805]
C122  100nF  [C 0402]
C123  100nF  [C 0402]
C124  100nF  [C 0402]
C125  6pF  [C 0402]
C126  100nF  [C 0402]
C127  100nF  [C 0402]
C128  6pF  [C 0402]
J10  HR911105A  [RJ-45A12]
L10  120R,2A  [L 0603]
L11  120R,2A  [L 0603]
R109  4.7K  [R 0402]
R112  4.7K  [R 0402]
R113  4.7K  [R 0402]
R115  4.7K  [R 0402]
R116  4.7K  [R 0402]
R117  4.7K  [R 0402]
R118  22R  [R 0402]
R119  1.5K  [R 0402]
R120  1.5K  [R 0402]
R122  4.7K  [R 0402]
R123  NC/4.7K  [R 0402]
R124  2.49K 1%  [R 0402]
R125  510R  [R 0402]
R126  510R  [R 0402]
U26  YT8512C  [YT8512C]
U27  AZ1143-04F  [DFN2510P10E]
X3  25MHz  [XTAL-3225]

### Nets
GND: C118.2 C119.2 C120.1 C121.1 C122.1 C123.1 C124.1 C125.2 C126.1 C127.1 C128.2 J10.8(CHSGND) J10.13(SHILED) J10.14(SHILED) R109.1 R113.1 R116.1 R124.1 R125.1 U26.33(EPAD) U27.3(GND) U27.8(GND) X3.2(GND) X3.4(GND)
VCC3V3_SYS: L10.1 L11.1
VCCA3V3_RMII: C118.1 C119.1 L10.2 U26.7(AVDD33) U26.30(NC/AVDD33)
VCCIO_RMII: C120.2 C121.2 L11.2 R112.1 R115.1 R117.1 R119.1 R120.1 R122.1 R123.1 R126.2 U26.14(DVDD33)
PHY1_LED0/PHYAD0: J10.11(LED(Y)-) R117.2 U26.24(LED0/PHYADD0)
PHY1_LED1/PHYAD1: J10.9(LED(G)+) R116.2 U26.25(LED1/PHYADD1)
PHY1_TRX0_N: J10.2(TD-) U26.4(TRXN0) U27.2(LINE2) U27.9(NC)
PHY1_TRX0_P: J10.1(TD+) U26.3(TRXP0) U27.1(LINE1) U27.10(NC)
PHY1_TRX1_N: J10.6(RD-) U26.6(TRXN1) U27.5(LINE4) U27.6(NC)
PHY1_TRX1_P: J10.3(RD+) U26.5(TRXP1) U27.4(LINE3) U27.7(NC)
PHY1_XTALIN: C125.1 U26.31(XTAL_IN) X3.1(IN)
PHY1_XTALOUT: C128.1 U26.32(XTAL_OUT) X3.3(OUT)
RMII_CLK: R118.1  [project net GPIO1_D5]
RMII_MDC: R120.2 U26.22(MDC)  [project net GPIO1_C7]
RMII_MDIO: R119.2 U26.23(MDIO)  [project net GPIO1_D0]
RMII_RESET: C122.2 R123.2 U26.21(RESET_N)  [project net GPIO2_A1]
RMII_RXD0: U26.9(RXD0)  [project net GPIO1_D4]
RMII_RXD1: R109.2 U26.10(RXD1)  [project net GPIO1_D7]
RMII_RXDV_CRS: U26.26(CRS/CRS_DV)  [project net GPIO1_D6]
RMII_RXER: U26.28(RX_ER)  [project net GPIO2_A0]
RMII_TXD0: U26.16(TXD0)  [project net GPIO1_D1]
RMII_TXD1: U26.17(TXD1)  [project net GPIO1_D2]
RMII_TXEN: U26.20(TX_EN)  [project net GPIO1_D3]
NetC123_2: C123.2 U26.2(AVDDL_REG)
NetC124_2: C124.2 U26.29(DVDDL_REG)
NetC126_2: C126.2 J10.4(TCT)
NetC127_2: C127.2 J10.5(RCT)
NetJ10_10: J10.10(LED(G)-) R125.2
NetJ10_12: J10.12(LED(Y)+) R126.1
NetR112_2: R112.2 U26.11(RXD2/INT_N)
NetR113_2: R113.2 U26.12(RXD3/CLK_CTL)
NetR115_2: R115.2 U26.8(RX_DV)
NetR118_2: R118.2 U26.15(TXC)
NetR122_2: R122.2 U26.27(COL)
NetR124_2: R124.2 U26.1(RBIAS)

Not connected (* = marked no-connect by the designer): J10 7(NC)*; U26 13(RXC)* 18(TXD2)* 19(TXD3)*

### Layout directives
differential pair: PHY1_TRX0_N, PHY1_TRX0_P, PHY1_TRX1_N, PHY1_TRX1_P

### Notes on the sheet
- PHY RMII
- Interrupt
- (near R109) LED Mode
- (near R115) RMII Mode
- TXC Output Mode
- PHY Address Config
- PHY Address
- PHYAD[1:0]
- 1(default)
- 2'b01
- (near R123) DNP

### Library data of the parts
C118-C128 = C: 无极性电容; BOM名称: 无极性贴片电容; 版权归属: 正点原子
J10 = RJ45 HR911105A-ATK: 带灯以太网接口; 版权归属: 正点原子; Parameter: 接口器件
L10 L11 = L: 小功率贴片电感磁珠; 版权归属: 正点原子
R109 R112 R113 R115-R120 R122-R126 = R: 电阻; BOM名称: 贴片电阻; 版权归属: 正点原子
U26 = YT8512C: 10M/100M 网络PHY RMII/MII
U27 = AZ1143-04F: ESD保护二极管阵列
X3 = XTAL-4P: as X2 on sheet 06_ATK-DLRK3562JB_4G_HUB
